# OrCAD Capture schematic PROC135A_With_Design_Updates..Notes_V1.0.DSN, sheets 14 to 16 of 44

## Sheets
14 14. SOC POWER: size C; title: SOC POWER
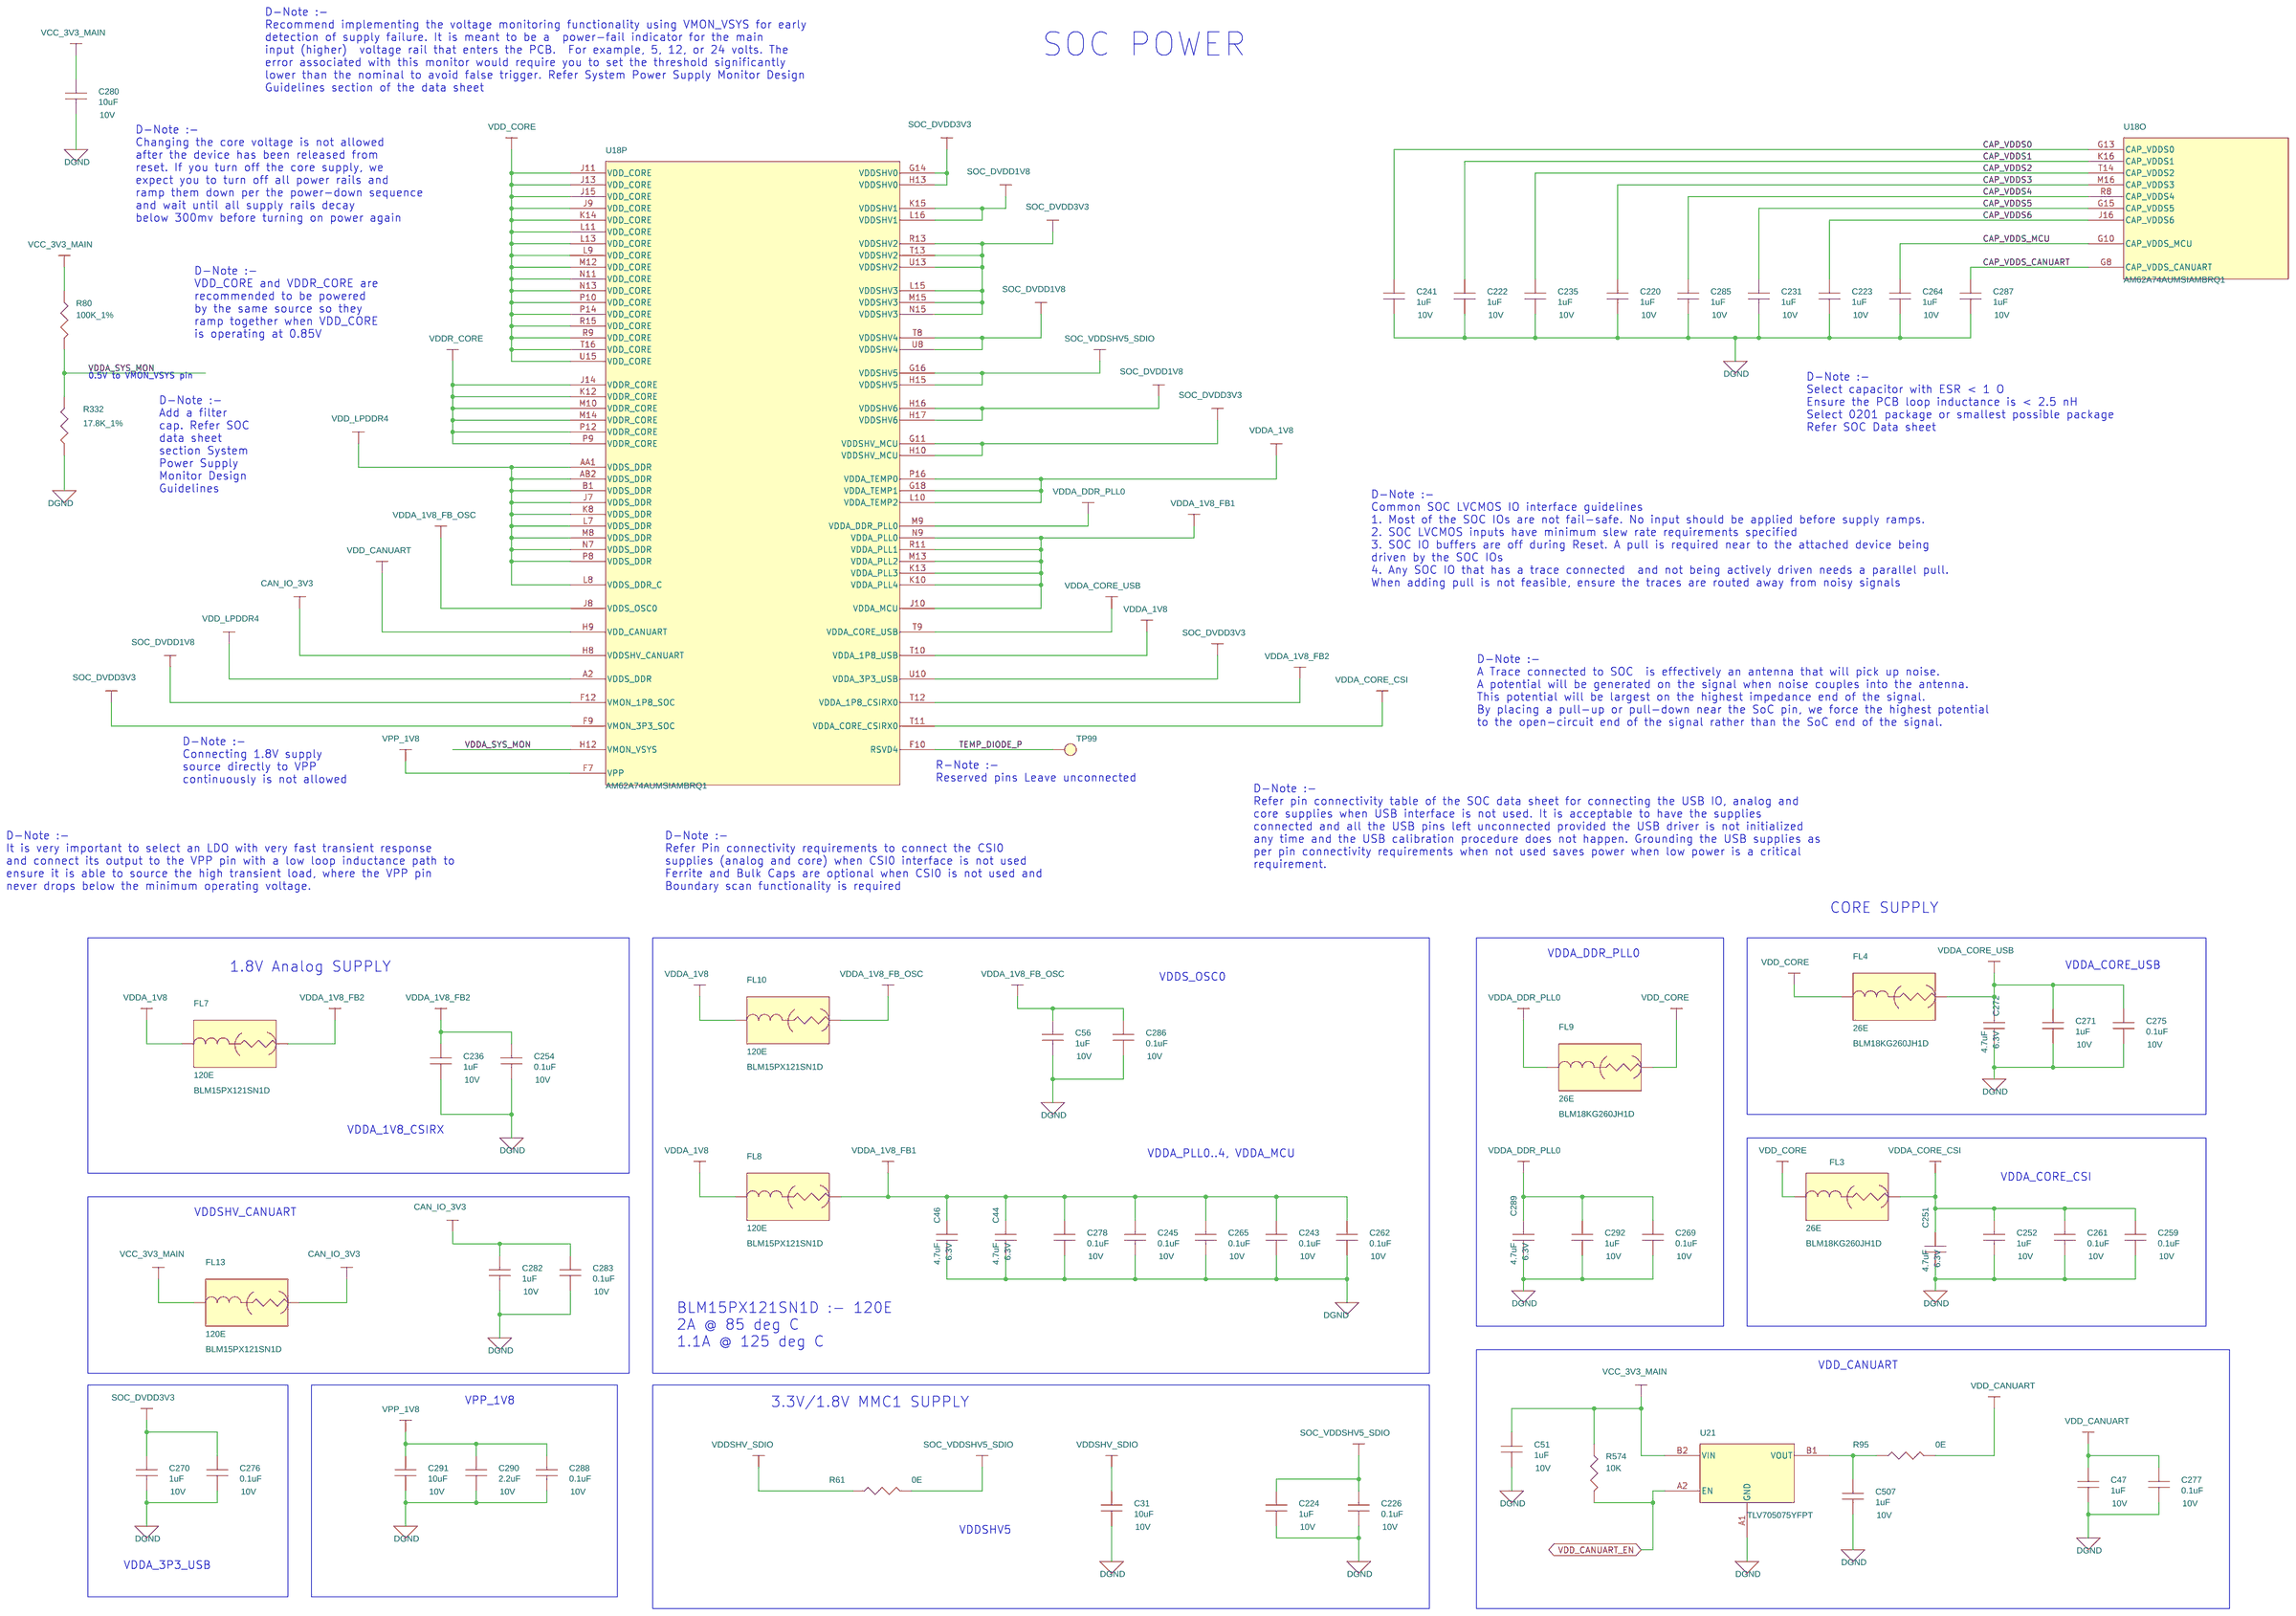
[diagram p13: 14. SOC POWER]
15 15. SOC POWER CAPS: size C; title: SOC POWER CAPS & SOC VSS
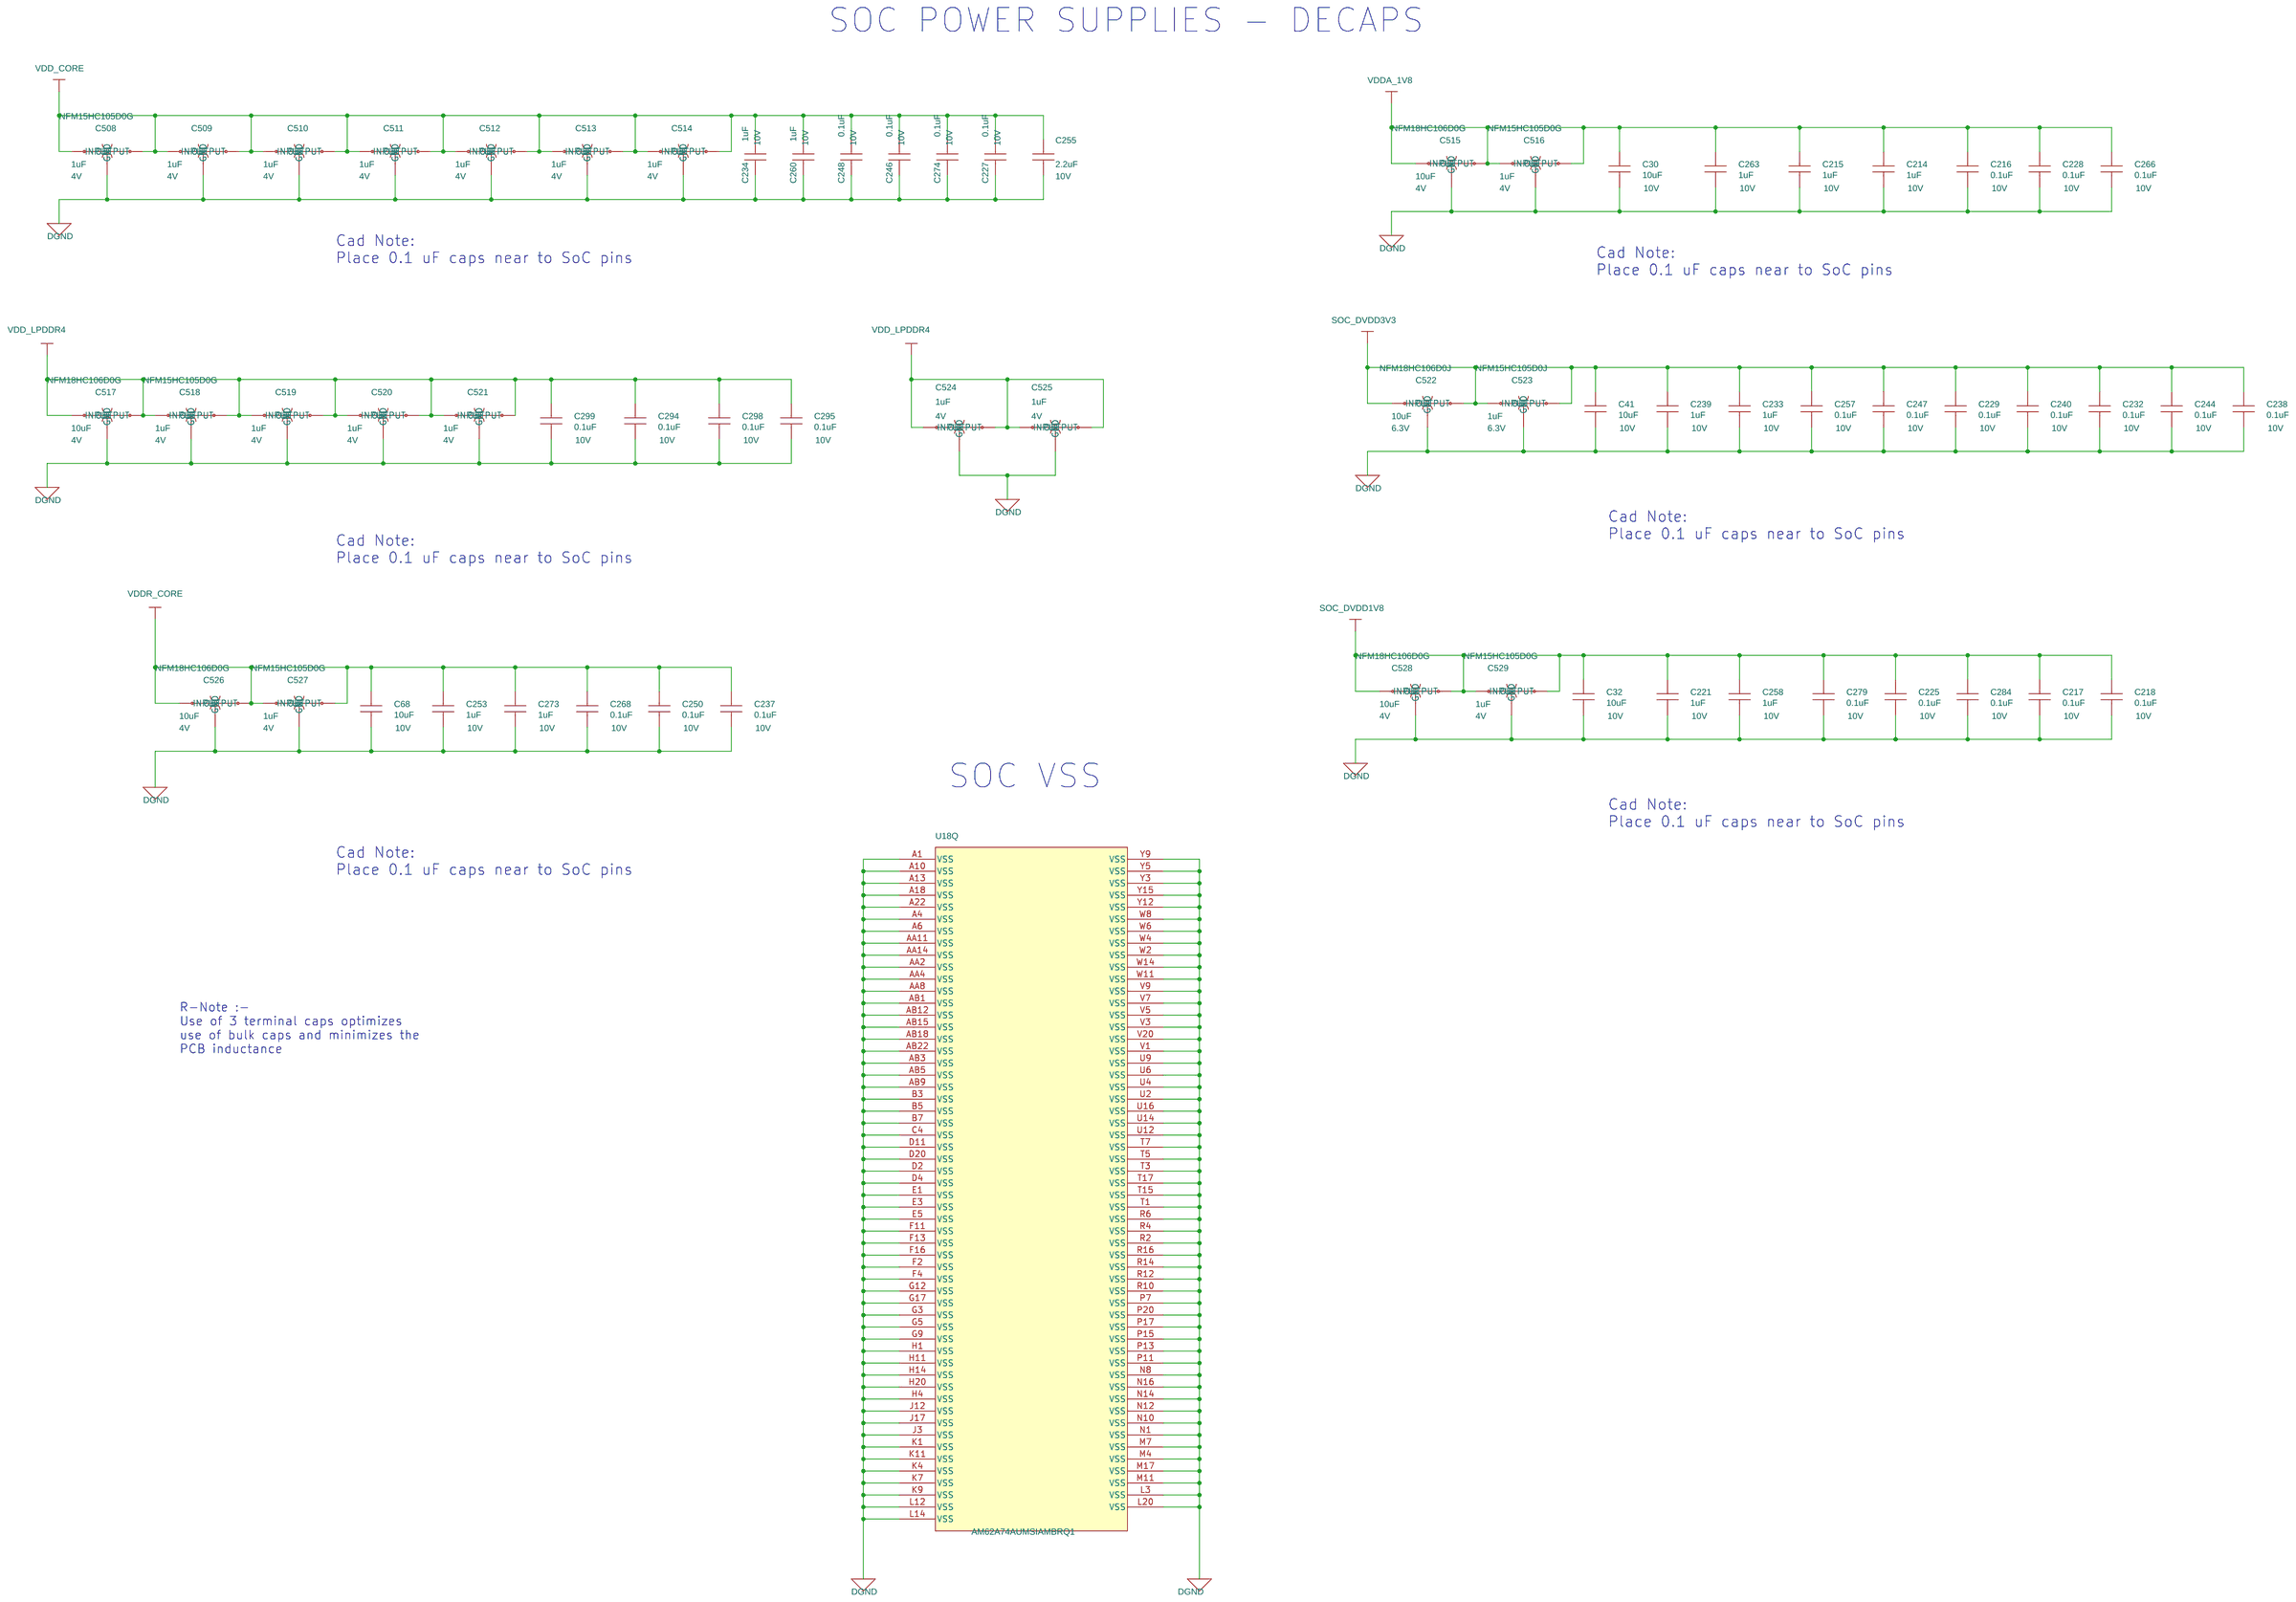
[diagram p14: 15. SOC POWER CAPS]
16 16. LPDDR4 INTERFACE: size C; title: SOC LPDDR4 INTERFACE
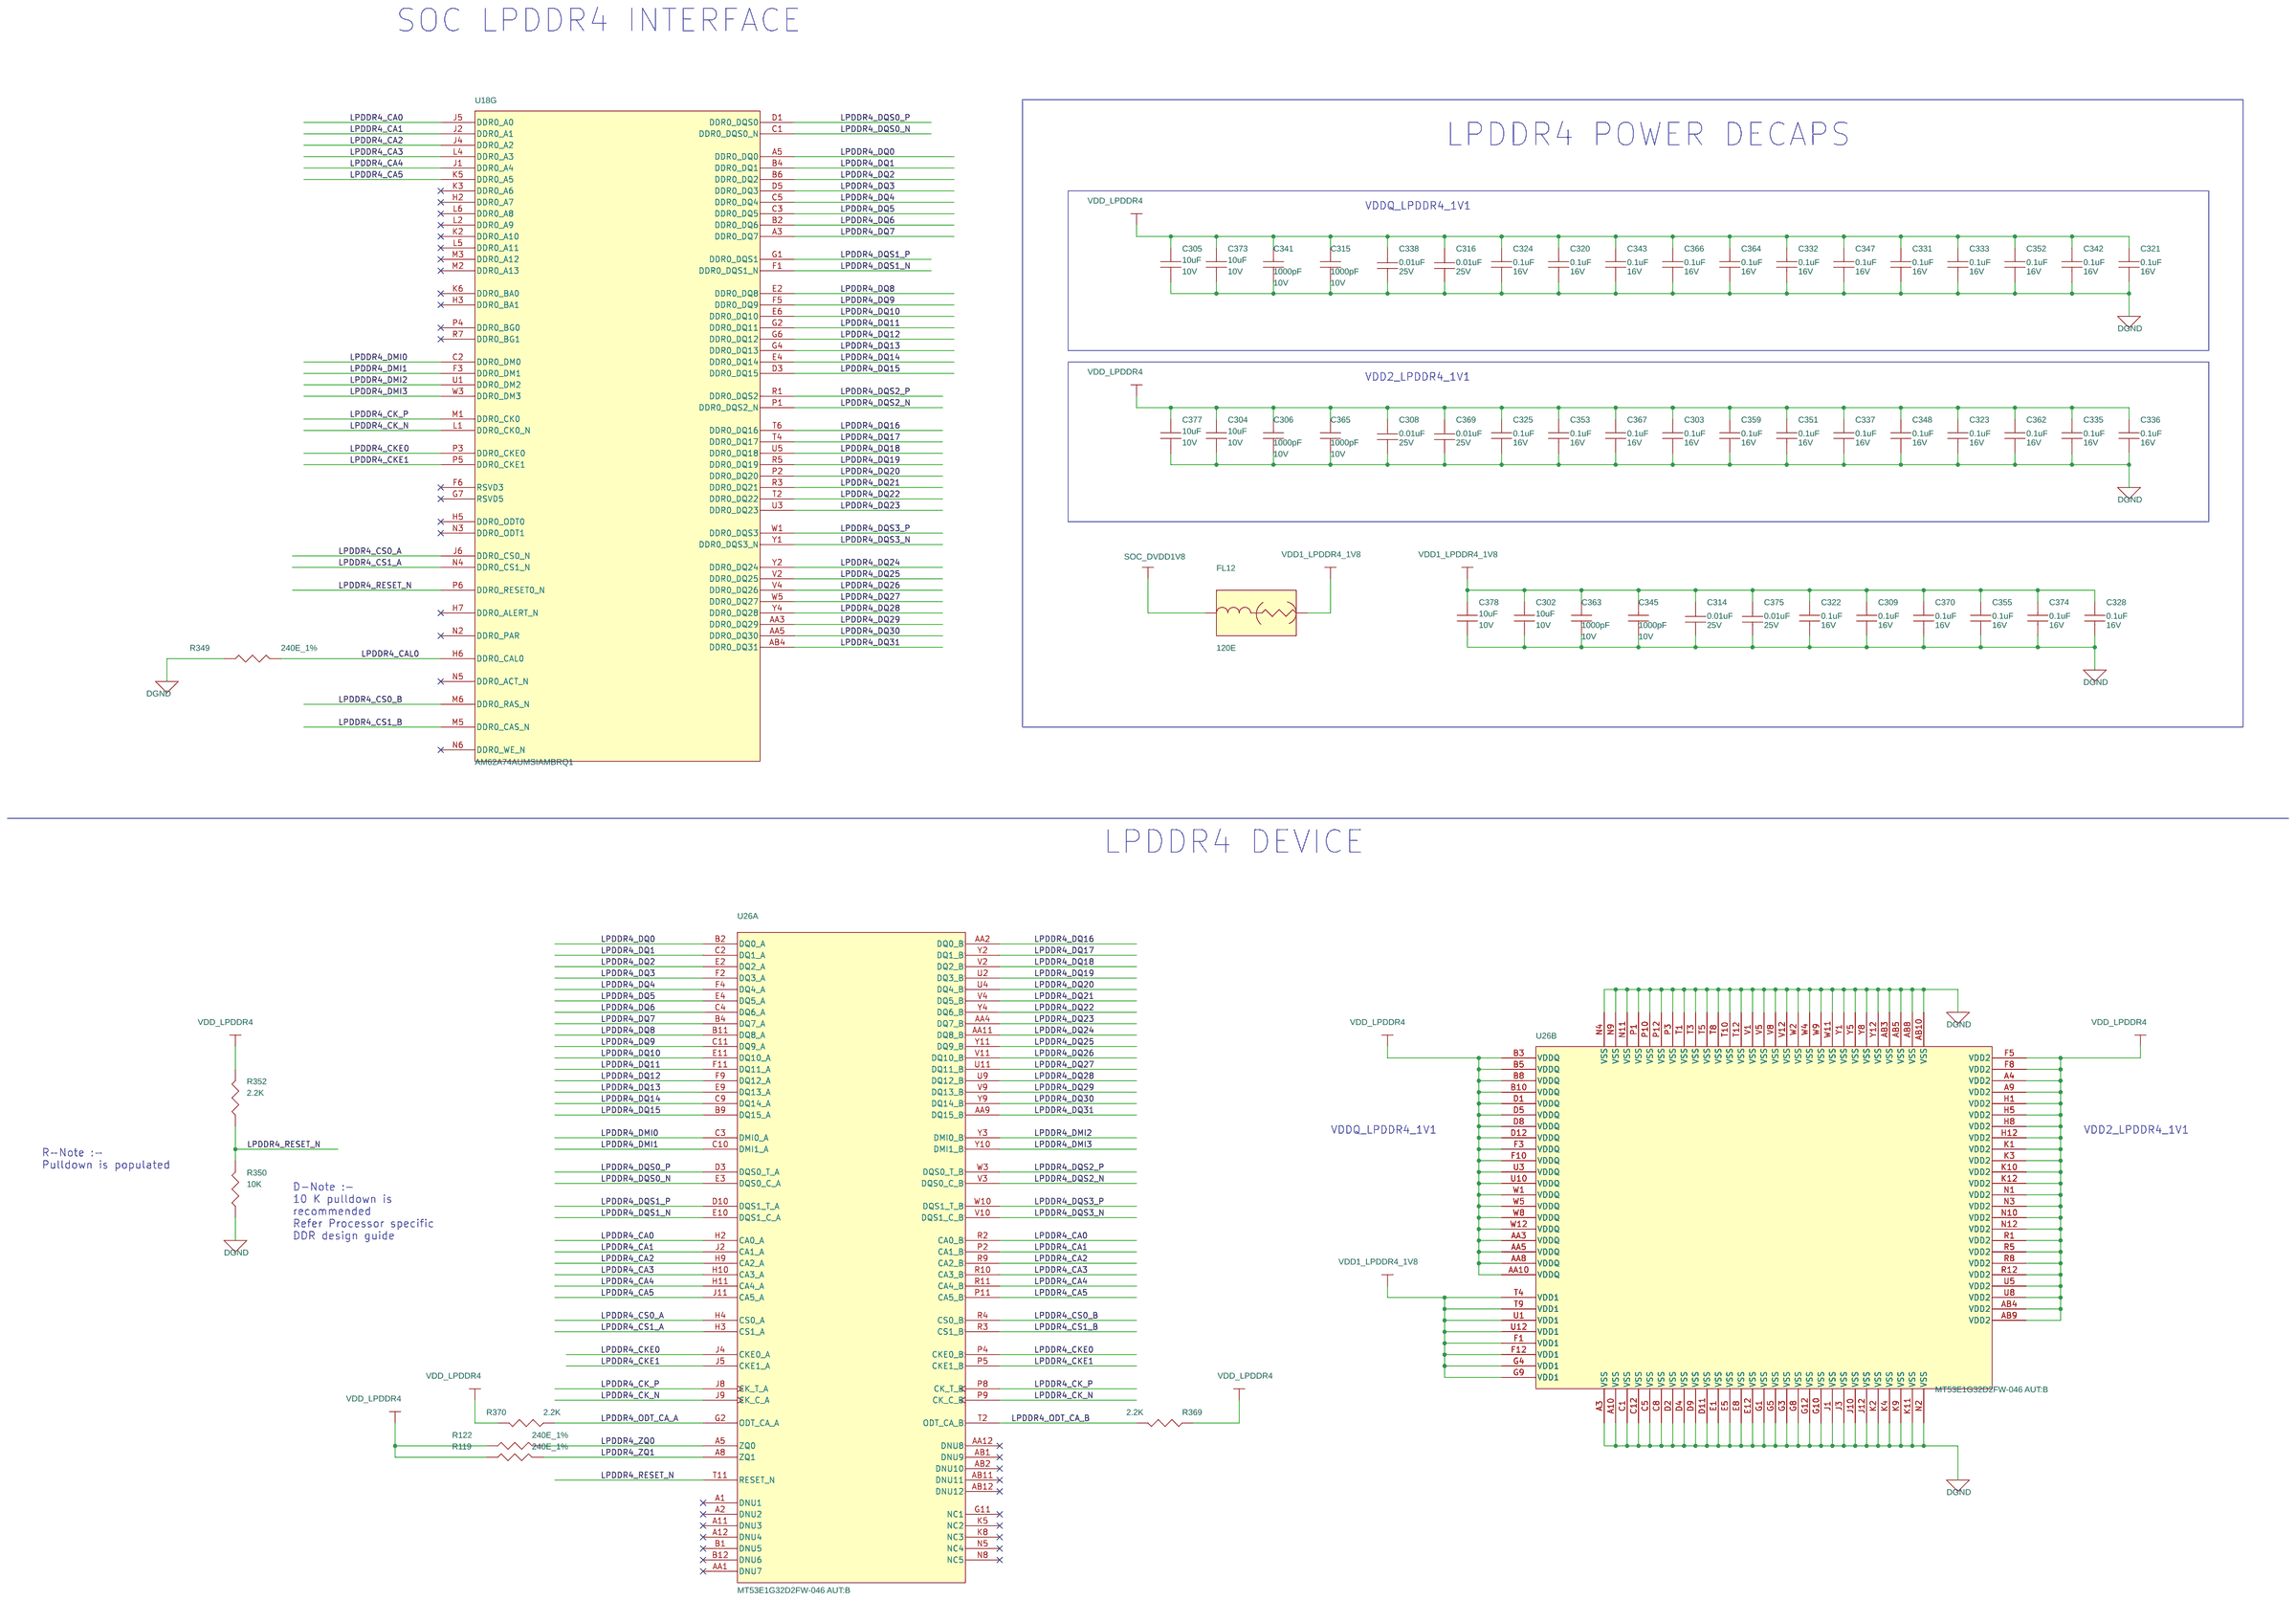
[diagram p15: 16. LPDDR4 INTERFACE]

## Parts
sheet 14. SOC POWER
C31  10uF  [CAP0402_1]
C44  4.7uF  [CAP0201_0-5]
C46  4.7uF  [CAP0201_0-5]
C47  1uF  [CAP0201_0-5]
C51  1uF  [CAP0201_0-5]
C56  1uF  [CAP0201_0-5]
C220  1uF  [CAP0201_0-5]
C222  1uF  [CAP0201_0-5]
C223  1uF  [CAP0201_0-5]
C224  1uF  [CAP0201_0-5]
C226  0.1uF  [CAP0201_0-5]
C231  1uF  [CAP0201_0-5]
C235  1uF  [CAP0201_0-5]
C236  1uF  [CAP0201_0-5]
C241  1uF  [CAP0201_0-5]
C243  0.1uF  [CAP0201_0-5]
C245  0.1uF  [CAP0201_0-5]
C251  4.7uF  [CAP0201_0-5]
C252  1uF  [CAP0201_0-5]
C254  0.1uF  [CAP0201_0-5]
C259  0.1uF  [CAP0201_0-5]
C261  0.1uF  [CAP0201_0-5]
C262  0.1uF  [CAP0201_0-5]
C264  1uF  [CAP0201_0-5]
C265  0.1uF  [CAP0201_0-5]
C269  0.1uF  [CAP0201_0-5]
C270  1uF  [CAP0201_0-5]
C271  1uF  [CAP0201_0-5]
C272  4.7uF  [CAP0201_0-5]
C275  0.1uF  [CAP0201_0-5]
C276  0.1uF  [CAP0201_0-5]
C277  0.1uF  [CAP0201_0-5]
C278  0.1uF  [CAP0201_0-5]
C280  10uF  [CAP0402_1]
C282  1uF  [CAP0201_0-5]
C283  0.1uF  [CAP0201_0-5]
C285  1uF  [CAP0201_0-5]
C286  0.1uF  [CAP0201_0-5]
C287  1uF  [CAP0201_0-5]
C288  0.1uF  [CAP0201_0-5]
C289  4.7uF  [CAP0201_0-5]
C290  2.2uF  [CAP0201_0-5]
C291  10uF  [CAP0402_1]
C292  1uF  [CAP0201_0-5]
C507  1uF  [CAP0201_0-5]
FL3  26E  [EMIFIL_BLM18P_0603_0-8]
FL4  26E  [EMIFIL_BLM18P_0603_0-8]
FL7  120E  [EMIFIL_BLM15A_0402_0-6]
FL8  120E  [EMIFIL_BLM15A_0402_0-6]
FL9  26E  [EMIFIL_BLM18P_0603_0-8]
FL10  120E  [EMIFIL_BLM15A_0402_0-6]
FL13  120E  [EMIFIL_BLM15A_0402_0-6]
R61  0E  [RES0402_0-5]
R80  100K_1%  [RES0402_0-5]
R95  0E  [RES0402_0-5]
R332  17.8K_1%  [RES0402_0-5]
R574  10K  [RES0201_0-5]
TP99  TP20_SMD  [TP20_SMD]
U21  TLV705075YFPT  [DSBGA4_15-74_30X30_0-5]
sheet 15. SOC POWER CAPS
C30  10uF  [CAP0402_1]
C32  10uF  [CAP0402_1]
C41  10uF  [CAP0402_1]
C68  10uF  [CAP0402_1]
C214  1uF  [CAP0201_0-5]
C215  1uF  [CAP0201_0-5]
C216  0.1uF  [CAP0201_0-5]
C217  0.1uF  [CAP0201_0-5]
C218  0.1uF  [CAP0201_0-5]
C221  1uF  [CAP0201_0-5]
C225  0.1uF  [CAP0201_0-5]
C227  0.1uF  [CAP0201_0-5]
C228  0.1uF  [CAP0201_0-5]
C229  0.1uF  [CAP0201_0-5]
C232  0.1uF  [CAP0201_0-5]
C233  1uF  [CAP0201_0-5]
C234  1uF  [CAP0201_0-5]
C237  0.1uF  [CAP0201_0-5]
C238  0.1uF  [CAP0201_0-5]
C239  1uF  [CAP0201_0-5]
C240  0.1uF  [CAP0201_0-5]
C244  0.1uF  [CAP0201_0-5]
C246  0.1uF  [CAP0201_0-5]
C247  0.1uF  [CAP0201_0-5]
C248  0.1uF  [CAP0201_0-5]
C250  0.1uF  [CAP0201_0-5]
C253  1uF  [CAP0201_0-5]
C255  2.2uF  [CAP0201_0-5]
C257  0.1uF  [CAP0201_0-5]
C258  1uF  [CAP0201_0-5]
C260  1uF  [CAP0201_0-5]
C263  1uF  [CAP0201_0-5]
C266  0.1uF  [CAP0201_0-5]
C268  0.1uF  [CAP0201_0-5]
C273  1uF  [CAP0201_0-5]
C274  0.1uF  [CAP0201_0-5]
C279  0.1uF  [CAP0201_0-5]
C284  0.1uF  [CAP0201_0-5]
C294  0.1uF  [CAP0201_0-5]
C295  0.1uF  [CAP0201_0-5]
C298  0.1uF  [CAP0201_0-5]
C299  0.1uF  [CAP0201_0-5]
C508  1uF  [EMIFIL_NFM15CC_0402_0-5]
C509  1uF  [EMIFIL_NFM15CC_0402_0-5]
C510  1uF  [EMIFIL_NFM15CC_0402_0-5]
C511  1uF  [EMIFIL_NFM15CC_0402_0-5]
C512  1uF  [EMIFIL_NFM15CC_0402_0-5]
C513  1uF  [EMIFIL_NFM15CC_0402_0-5]
C514  1uF  [EMIFIL_NFM15CC_0402_0-5]
C515  10uF  [EMIFIL_NFM18C_0603_0-7]
C516  1uF  [EMIFIL_NFM15CC_0402_0-5]
C517  10uF  [EMIFIL_NFM18C_0603_0-7]
C518  1uF  [EMIFIL_NFM15CC_0402_0-5]
C519  1uF  [EMIFIL_NFM15CC_0402_0-5]
C520  1uF  [EMIFIL_NFM15CC_0402_0-5]
C521  1uF  [EMIFIL_NFM15CC_0402_0-5]
C522  10uF  [EMIFIL_NFM18C_0603_0-7]
C523  1uF  [EMIFIL_NFM15CC_0402_0-5]
C524  1uF  [EMIFIL_NFM15CC_0402_0-5]
C525  1uF  [EMIFIL_NFM15CC_0402_0-5]
C526  10uF  [EMIFIL_NFM18C_0603_0-7]
C527  1uF  [EMIFIL_NFM15CC_0402_0-5]
C528  10uF  [EMIFIL_NFM18C_0603_0-7]
C529  1uF  [EMIFIL_NFM15CC_0402_0-5]
sheet 16. LPDDR4 INTERFACE
C302  10uF  [CAP0402_0-75]
C303  0.1uF  [CAP0201_0-5]
C304  10uF  [CAP0402_0-75]
C305  10uF  [CAP0402_0-75]
C306  1000pF  [CAP0201_0-5]
C308  0.01uF  [CAP0201_0-5]
C309  0.1uF  [CAP0201_0-5]
C314  0.01uF  [CAP0201_0-5]
C315  1000pF  [CAP0201_0-5]
C316  0.01uF  [CAP0201_0-5]
C320  0.1uF  [CAP0201_0-5]
C321  0.1uF  [CAP0201_0-5]
C322  0.1uF  [CAP0201_0-5]
C323  0.1uF  [CAP0201_0-5]
C324  0.1uF  [CAP0201_0-5]
C325  0.1uF  [CAP0201_0-5]
C328  0.1uF  [CAP0201_0-5]
C331  0.1uF  [CAP0201_0-5]
C332  0.1uF  [CAP0201_0-5]
C333  0.1uF  [CAP0201_0-5]
C335  0.1uF  [CAP0201_0-5]
C336  0.1uF  [CAP0201_0-5]
C337  0.1uF  [CAP0201_0-5]
C338  0.01uF  [CAP0201_0-5]
C341  1000pF  [CAP0201_0-5]
C342  0.1uF  [CAP0201_0-5]
C343  0.1uF  [CAP0201_0-5]
C345  1000pF  [CAP0201_0-5]
C347  0.1uF  [CAP0201_0-5]
C348  0.1uF  [CAP0201_0-5]
C351  0.1uF  [CAP0201_0-5]
C352  0.1uF  [CAP0201_0-5]
C353  0.1uF  [CAP0201_0-5]
C355  0.1uF  [CAP0201_0-5]
C359  0.1uF  [CAP0201_0-5]
C362  0.1uF  [CAP0201_0-5]
C363  1000pF  [CAP0201_0-5]
C364  0.1uF  [CAP0201_0-5]
C365  1000pF  [CAP0201_0-5]
C366  0.1uF  [CAP0201_0-5]
C367  0.1uF  [CAP0201_0-5]
C369  0.01uF  [CAP0201_0-5]
C370  0.1uF  [CAP0201_0-5]
C373  10uF  [CAP0402_0-75]
C374  0.1uF  [CAP0201_0-5]
C375  0.01uF  [CAP0201_0-5]
C377  10uF  [CAP0402_0-75]
C378  10uF  [CAP0402_0-75]
FL12  120E  [EMIFIL_BLM15A_0402_0-6]
R119  240E_1%  [RES0402_0-5]
R122  240E_1%  [RES0402_0-5]
R349  240E_1%  [RES0402_0-5]
R350  10K  [RES0402_0-5]
R352  2.2K  [RES0402_0-5]
R369  2.2K  [RES0402_0-5]
R370  2.2K  [RES0402_0-5]
U26  MT53E1G32D2FW-046 AUT:B  [WFBGA200_MT53E2G32D4DE_400X570_1-2]  (sections A,B)
sheet 41. OSCILLATOR
U18  AM62A74AUMSIAMBRQ1  [FBGA484_31-49_710X710_2-7]  (sections A,B,C,D,E,F,G,H,I,J,K,L,M,N,O,P,Q)

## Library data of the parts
C30-C32 C41 C68 C280 C291 = CAP: CAP CERAMIC 10uF 10V 20% X5R 0402; Chkd/date: MANIRAJA/150219; Crtd /date: ALVY/150219; Custom_Duty: 15%; Customs_HS_Code: 85322990; Distributor_name: DIGIKEY; Distributor_part_number: 1276-6830-1-ND; Footprint Path: Y:\MIS_DATABASE\Library\ALTIUM_TOOL\PCB_FOOTPRINTS\Altium_Footprint_Lib.PcbLib; Height: 0.90MM; Library Path: Y:\MIS_DATABASE\Library\ALTIUM_TOOL\SCHEMATICS_PARTS\MS_DISCRETE_Library.schlib; Mfr_name: SAMSUNG; Mfr_part_number: CL05A106MP8NUB8; Mistral Part No: 120019020008-R; Package: 0402; Part_type: CAPACITORS\CERAMIC; Project: TI_60GHz-AOP; RoHS: RoHS; Temperature: -55°C+85°C; Tolerance: 20%; Voltage: 10V; Wattage: NA; Weight: NA; Datasheet: Y:\MIS_DATABASE\DATASHEETS\CAPACITORS\CL05A106MP8NUB8.PDF
C44 C46 C251 C272 C289 = CAP: CAP CERAMIC 4.7uF 6.3V 20% X5R 0201; Chkd/date: ALVY/020522; Crtd /date: TAMILARASU/020522; Custom_Duty: 15%; Customs_HS_Code: 85322990; Distributor_name: NA; Distributor_part_number: NA; Footprint Path: Y:\MIS_DATABASE\Library\ALTIUM_TOOL\PCB_FOOTPRINTS\Altium_Footprint_Lib.PcbLib; Height: 0.33MM; Library Path: Y:\MIS_DATABASE\Library\ALTIUM_TOOL\SCHEMATICS_PARTS\MS_DISCRETE_Library.schlib; Mfr_name: CAL-CHIP; Mfr_part_number: GMC02X5R475M6R3NT; Mistral Part No: 120022050001-R; Package: 0201; Part_type: CAPACITORS\CERAMIC; Project: TI_AM62A_SK_EVM; RoHS: RoHS; Temperature: -55°C+85°C; Tolerance: 20%; Voltage: 6.3V; Wattage: NA; Weight: NA; Datasheet: Y:\MIS_DATABASE\DATASHEETS\CAPACITORS\CALCHIP-GMC-SER.PDF
C47 C51 C56 C214 C215 C220-C224 C231 C233-C236 C239 C241 C252 C253 C258 C260 C263 C264 C270 C271 C273 C282 C285 C287 C292 C507 = CAP: CAP CERAMIC 1uF 10V 20% X5R 0201; Chkd/date: NAVEED/070415; Crtd /date: VASANTHA/230314; Custom_Duty: 15%; Customs_HS_Code: 85322990; Distributor_name: DIGIKEY; Distributor_part_number: 1276-1324-1-ND; Footprint Path: Y:\MIS_DATABASE\Library\ALTIUM_TOOL\PCB_FOOTPRINTS\Altium_Footprint_Lib.PcbLib; Height: 0.35MM; Library Path: Y:\MIS_DATABASE\Library\ALTIUM_TOOL\SCHEMATICS_PARTS\MS_DISCRETE_Library.schlib; Mfr_name: SAMSUNG; Mfr_part_number: CL03A105MP3NSNC; Mistral Part No: 120015030003-R; Package: 0201; Part_type: CAPACITORS\CERAMIC; Project: DUET BOARDS; RoHS: RoHS; Temperature: -55°C+85°C; Tolerance: 20%; Voltage: 10V; Wattage: NA; Weight: 0.17mg; Datasheet: Y:\MIS_DATABASE\DATASHEETS\CAPACITORS\CL03A105MP3NSNC.PDF
C216-C218 C225-C229 C232 C237 C238 C240 C243-C248 C250 C254 C257 C259 C261 C262 C265 C266 C268 C269 C274-C279 C283 C284 C286 C294 C295 C298 C299 = CAP: CAP CERAMIC 0.1uF 10V 10% X5R 0201; Chkd/date: MANIRAJA/290421; Crtd /date: ALVY/290421; Custom_Duty: 15%; Customs_HS_Code: 85322990; Distributor_name: DIGIKEY; Distributor_part_number: 1276-1115-1-ND; Footprint Path: Y:\MIS_DATABASE\Library\ALTIUM_TOOL\PCB_FOOTPRINTS\Altium_Footprint_Lib.PcbLib; Height: 0.33MM; Library Path: Y:\MIS_DATABASE\Library\ALTIUM_TOOL\SCHEMATICS_PARTS\MS_DISCRETE_Library.schlib; Mfr_name: SAMSUNG; Mfr_part_number: CL03A104KP3NNNC; Mistral Part No: 120009050017-R; Package: 0201; Part_type: CAPACITORS\CERAMIC; Project: SRMS-SAR_BRD; RoHS: RoHS; Temperature: -55°C+85°C; Tolerance: 10%; Voltage: 10V; Wattage: NA; Weight: 0.33mg; Datasheet: Y:\MIS_DATABASE\DATASHEETS\CAPACITORS\CL03A104KP3NNNC.PDF
C288 = CAP: CAP CERAMIC 0.1uF 10V 20% X5R 0201; Chkd/date: RAGESH/290910; Crtd /date: MUDDU/290410; Custom_Duty: 15%; Customs_HS_Code: 85322990; Distributor_name: DIGIKEY; Distributor_part_number: 490-5405-1-ND; Footprint Path: Y:\MIS_DATABASE\Library\ALTIUM_TOOL\PCB_FOOTPRINTS\Altium_Footprint_Lib.PcbLib; Height: 0.33MM; Library Path: Y:\MIS_DATABASE\Library\ALTIUM_TOOL\SCHEMATICS_PARTS\MS_DISCRETE_Library.schlib; Mfr_name: MURATA; Mfr_part_number: GRM033R61A104ME15D; Mistral Part No: 120010040004-R; Package: 0201; Part_type: CAPACITORS\CERAMIC; Project: BUG_BASE-II; RoHS: RoHS; Temperature: -55°C+85°C; Tolerance: 20%; Voltage: 10V; Wattage: NA; Weight: 0.33mg; Datasheet: Y:\MIS_DATABASE\DATASHEETS\CAPACITORS\MURATA-GXX-SER_NOV17.PDF
C290 = CAP: CAP CERAMIC 2.2uF 10V 20% X5R 0201; Chkd/date: MANIRAJA/270519; Crtd /date: ALVY/230519; Custom_Duty: 15%; Customs_HS_Code: 85322990; Distributor_name: DIGIKEY; Distributor_part_number: 490-13228-1-ND; Footprint Path: Y:\MIS_DATABASE\Library\ALTIUM_TOOL\PCB_FOOTPRINTS\Altium_Footprint_Lib.PcbLib; Height: 0.39MM; Library Path: Y:\MIS_DATABASE\Library\ALTIUM_TOOL\SCHEMATICS_PARTS\MS_DISCRETE_Library.schlib; Mfr_name: MURATA; Mfr_part_number: GRM033R61A225ME47D; Mistral Part No: 120019050028-R; Package: 0201; Part_type: CAPACITORS\CERAMIC; Project: BRUKER_SD820_COMMONDO; RoHS: RoHS; Temperature: -55°C+85°C; Tolerance: 20%; Voltage: 10V; Wattage: NA; Weight: 0.33mg; Datasheet: Y:\MIS_DATABASE\DATASHEETS\CAPACITORS\GRM033R61A225ME47D.PDF
FL3 FL4 FL9 = EMIFILTER_IND: IND FERRITE BEAD CHIP 26E 4A 0603; Chkd/date: ALVY/020522; Crtd /date: TAMILARASU/020522; Custom_Duty: 24%; Customs_HS_Code: 85437099; Distributor_name: DIGIKEY; Distributor_part_number: 490-14026-1-ND; Footprint Path: Y:\MIS_DATABASE\Library\ALTIUM_TOOL\PCB_FOOTPRINTS\Altium_Footprint_Lib.PcbLib; Height: 0.75MM; Library Path: Y:\MIS_DATABASE\Library\ALTIUM_TOOL\SCHEMATICS_PARTS\MS_FILTER_Library.schlib; Mfr_name: MURATA; Mfr_part_number: BLM18KG260JH1D; Mistral Part No: 130022050001-R; Package: 0603; Part_type: INDUCTOR; Project: TI_AM62A_SK_EVM; RoHS: RoHS; Temperature: -55°C+150°C; Tolerance: 25%; Voltage: NA; Wattage: NA; Weight: 4mg; Datasheet: Y:\MIS_DATABASE\DATASHEETS\DISCRETES\INDUCTORS\BLM18XX-B-J-H1D.PDF
FL7 FL8 FL10 FL12 FL13 = EMIFILTER_IND: IND FERRITE BEAD CHIP 120E 2A 0402; Chkd/date: NAVEED/241114; Crtd /date: USMAN/170613; Custom_Duty: 24%; Customs_HS_Code: 85369090; Distributor_name: DIGIKEY; Distributor_part_number: 490-9656-1-ND; Footprint Path: Y:\MIS_DATABASE\Library\ALTIUM_TOOL\PCB_FOOTPRINTS\Altium_Footprint_Lib.PcbLib; Height: 0.55MM; Library Path: Y:\MIS_DATABASE\Library\ALTIUM_TOOL\SCHEMATICS_PARTS\MS_FILTER_Library.schlib; Mfr_name: MURATA; Mfr_part_number: BLM15PX121SN1D; Mistral Part No: 130013060022-R; Package: 0402; Part_type: INDUCTOR; Project: GEN_3-8; RoHS: RoHS; Temperature: -55°C+125°C; Tolerance: 25%; Voltage: NA; Wattage: NA; Weight: 1mg; Datasheet: Y:\MIS_DATABASE\DATASHEETS\DISCRETES\INDUCTORS\BLM15-SN1-SER.PDF
R61 R95 = RESISTOR: RES 0E 1/10W JUMPER 0402; Chkd/date: VASANTHA/061216; Crtd /date: NAVEED/201014; Custom_Duty: 15%; Customs_HS_Code: 85332119; Distributor_name: DIGIKEY; Distributor_part_number: P0.0JCT-ND; Footprint Path: Y:\MIS_DATABASE\Library\ALTIUM_TOOL\PCB_FOOTPRINTS\Altium_Footprint_Lib.PcbLib; Height: 0.40MM; IBISSP_MODLES: VALUE REPEATING 2 TIME; Library Path: Y:\MIS_DATABASE\Library\ALTIUM_TOOL\SCHEMATICS_PARTS\MS_DISCRETE_Library.schlib; Mfr_name: PANASONIC-ECG; Mfr_part_number: ERJ-2GE0R00X; Mistral Part No: 110018030052-R; Package: 0402; Part_type: RESISTORS\FIXED; Project: AEGIS POM; RoHS: RoHS; Temperature: -55°C+155°C; Tolerance: NA; Voltage: NA; Wattage: 1/10W; Weight: 0.8mg; Datasheet: Y:\MIS_DATABASE\DATASHEETS\RESISTORS\PAN-ERJSER_NOV17.PDF
R80 = RESISTOR: RES 100K 1/10W 1% 0402; Chkd/date: VASANTHA/201216; Crtd /date: MAZHAR/130306; Custom_Duty: 15%; Customs_HS_Code: 85332119; Distributor_name: DIGIKEY; Distributor_part_number: P100KLCT-ND; Footprint Path: Y:\MIS_DATABASE\Library\ALTIUM_TOOL\PCB_FOOTPRINTS\Altium_Footprint_Lib.PcbLib; Height: 0.40MM; Library Path: Y:\MIS_DATABASE\Library\ALTIUM_TOOL\SCHEMATICS_PARTS\MS_DISCRETE_Library.schlib; Mfr_name: PANASONIC-ECG; Mfr_part_number: ERJ-2RKF1003X; Mistral Part No: 110009030187-R; Package: 0402; Part_type: RESISTORS\FIXED; Project: J32; RoHS: RoHS; Temperature: -55°C+155°C; Tolerance: 1%; Voltage: NA; Wattage: 1/10W; Weight: 0.8mg; Datasheet: Y:\MIS_DATABASE\DATASHEETS\RESISTORS\PAN-ERJSER_NOV17.PDF
R332 = RESISTOR: RES 17.8K 1/16W 1% 0402; Chkd/date: MANIRAJA/160218; Crtd /date: ALVY/150218; Custom_Duty: 15%; Customs_HS_Code: 85332119; Distributor_name: DIGIKEY; Distributor_part_number: 541-17.8KLCT-ND; Footprint Path: Y:\MIS_DATABASE\Library\ALTIUM_TOOL\PCB_FOOTPRINTS\Altium_Footprint_Lib.PcbLib; Height: 0.40MM; Library Path: Y:\MIS_DATABASE\Library\ALTIUM_TOOL\SCHEMATICS_PARTS\MS_DISCRETE_Library.schlib; Manufacturer: VISHAY; Mfr_name: VISHAY; Mfr_part_number: CRCW040217K8FKED; Mistral Part No: 110018020020-R; Package: 0402; Part_type: RESISTORS\FIXED; Project: DRDL_ITS2-SC; RoHS: RoHS; Temperature: -55°C+155°C; Tolerance: 1%; Voltage: NA; Wattage: 1/16W; Weight: 0.65mg; Datasheet: Y:\MIS_DATABASE\DATASHEETS\RESISTORS\CRCW0603.PDF
R574 = RESISTOR: RES 10K 1/20W 5% 0201; Chkd/date: MANIRAJA/050517; Crtd /date: MANIRAJA/050517; Custom_Duty: 15%; Customs_HS_Code: 85332119; Distributor_name: DIGIKEY; Distributor_part_number: 311-10KNCT-ND; Footprint Path: Y:\MIS_DATABASE\Library\ALTIUM_TOOL\PCB_FOOTPRINTS\Altium_Footprint_Lib.PcbLib; Height: 0.26MM; Library Path: Y:\MIS_DATABASE\Library\ALTIUM_TOOL\SCHEMATICS_PARTS\MS_DISCRETE_Library.schlib; Mfr_name: YAGEO AMERICA; Mfr_part_number: RC0201JR-0710KL; Mistral Part No: 110010070051-R; Package: 0201; Part_type: RESISTORS\FIXED; Project: GOLDEN-I LITE; RoHS: RoHS; Temperature: -55°C+125°C; Tolerance: 5%; Voltage: NA; Wattage: 1/20W; Weight: 0.17mg; Datasheet: Y:\MIS_DATABASE\DATASHEETS\RESISTORS\RCXXXXL-SER_MAR18.PDF
TP99 = TESTPOINT: TESTPOINT CIR 20 SMD; Chkd/date: SHREESHAIL/171006; Crtd /date: MAZHAR/171006; Custom_Duty: NA; Customs_HS_Code: NA; Distributor_name: NA; Distributor_part_number: NA; Footprint Path: Y:\MIS_DATABASE\Library\ALTIUM_TOOL\PCB_FOOTPRINTS\Altium_Footprint_Lib.PcbLib; Height: NA; Library Path: Y:\MIS_DATABASE\Library\ALTIUM_TOOL\SCHEMATICS_PARTS\MS_DISCRETE_Library.schlib; MECHANICAL 3D STEP FILE: NA; Mfr_name: LOCAL; Mistral Part No: NA; Package: SMD; Project: BT MODULE_CSRBC04; RoHS: NA; Temperature: NA; Tolerance: NA; Voltage: NA; Wattage: NA; Weight: NA; Datasheet: NA
U21 = TLV7050_DSBGA4: IC 200mA 0.75V LOW IQ LOW-DROPOUT REGULATOR DSBGA4; Chkd/date: ALVY/300522; Crtd /date: TAMILARASU/300522; Custom_Duty: 15%; Customs_HS_Code: 85423100; Distributor_name: DIGIKEY; Distributor_part_number: 296-TLV705075YFPTCT-ND; Footprint Path: Y:\MIS_DATABASE\Library\ALTIUM_TOOL\PCB_FOOTPRINTS\Altium_Footprint_Lib.PcbLib; Height: 0.50MM; Library Path: Y:\MIS_DATABASE\Library\ALTIUM_TOOL\SCHEMATICS_PARTS\MS_MISCPOWER_Library.schlib; Mfr_name: TEXAS INSTRUMENTS; Mistral Part No: 142022050034-R; Package: DSBGA4; Part_type: ICS\POWER\VOLTAGE REGULATOR; Project: TI_AM62A_SK_EVM; RoHS: RoHS; Temperature: -40°C+125°C; Tolerance: NA; Voltage: NA; Wattage: NA; Weight: 200mg; Datasheet: Y:\MIS_DATABASE\DATASHEETS\ICS\POWER\TLV705X.PDF
C255 = CAP: CAP CERAMIC 2.2uF 10V 10% X5R 0201; Chkd/date: MANIRAJA/220918; Crtd /date: MANIRAJA/220918; Custom_Duty: 15%; Customs_HS_Code: 85322990; Distributor_name: DIGIKEY; Distributor_part_number: 490-13227-1-ND; Footprint Path: Y:\MIS_DATABASE\Library\ALTIUM_TOOL\PCB_FOOTPRINTS\Altium_Footprint_Lib.PcbLib; Height: 0.39MM; Library Path: Y:\MIS_DATABASE\Library\ALTIUM_TOOL\SCHEMATICS_PARTS\MS_DISCRETE_Library.schlib; Mfr_name: MURATA; Mfr_part_number: GRM033R61A225KE47D; Mistral Part No: 120018090044-R; Package: 0201; Part_type: CAPACITORS\CERAMIC; Project: TI_60GHz-AOP; RoHS: RoHS; Temperature: -55°C+85°C; Tolerance: 10%; Voltage: 10V; Wattage: NA; Weight: 0.33mg; Datasheet: Y:\MIS_DATABASE\DATASHEETS\CAPACITORS\GRM033R61A225KE47D.PDF
C508-C514 C516 C518-C521 C524 C525 C527 C529 = CAP_NFM: PASSIVE FILTER EMI 1uF 4V AUTO 0402; Chkd/date: MANIRAJA/251018; Crtd /date: ALVY/251018; Custom_Duty: 15%; Customs_HS_Code: 85412900; Distributor_name: NA; Distributor_part_number: NA; Footprint Path: Y:\MIS_DATABASE\Library\ALTIUM_TOOL\PCB_FOOTPRINTS\Altium_Footprint_Lib.PcbLib; Height: 0.50MM; Library Path: Y:\MIS_DATABASE\Library\ALTIUM_TOOL\SCHEMATICS_PARTS\MS_FILTER_Library.schlib; Mfr_name: MURATA; Mfr_part_number: NFM15HC105D0G; Mistral Part No: 130018100050; Package: 0402; Part_type: FILTER; Project: TI_J7ES_EVM_SOM; RoHS: NA; Temperature: NA; Tolerance: NA; Voltage: 4V; Wattage: NA; Weight: NA; Datasheet: Y:\MIS_DATABASE\DATASHEETS\DISCRETES\INDUCTORS\NFM15CC223C1A3.PDF
C515 C517 C526 C528 = CAP_NFM: PASSIVE FILTER EMI 10uF 4V AUTO 0603; Chkd/date: MANIRAJA/251018; Crtd /date: ALVY/251018; Custom_Duty: 15%; Customs_HS_Code: 85412900; Distributor_name: NA; Distributor_part_number: NA; Footprint Path: Y:\MIS_DATABASE\Library\ALTIUM_TOOL\PCB_FOOTPRINTS\Altium_Footprint_Lib.PcbLib; Height: 0.70MM; Library Path: Y:\MIS_DATABASE\Library\ALTIUM_TOOL\SCHEMATICS_PARTS\MS_FILTER_Library.schlib; Mfr_name: MURATA; Mfr_part_number: NFM18HC106D0G; Mistral Part No: 130018100049; Package: 0603; Part_type: FILTER; Project: TI_J7ES_EVM_SOM; RoHS: NA; Temperature: NA; Tolerance: NA; Voltage: 4V; Wattage: NA; Weight: NA; Datasheet: Y:\MIS_DATABASE\DATASHEETS\DISCRETES\INDUCTORS\NFM18HC-SER.PDF
C522 = CAP_NFM: PASSIVE FILTER EMI 10uF 6.3V AUTO 0603; Chkd/date: MANIRAJA/280918; Crtd /date: ALVY/280918; Custom_Duty: 15%; Customs_HS_Code: 85412900; Distributor_name: NA; Distributor_part_number: NA; Footprint Path: Y:\MIS_DATABASE\Library\ALTIUM_TOOL\PCB_FOOTPRINTS\Altium_Footprint_Lib.PcbLib; Height: 0.70MM; Library Path: Y:\MIS_DATABASE\Library\ALTIUM_TOOL\SCHEMATICS_PARTS\MS_FILTER_Library.schlib; Mfr_name: MURATA; Mfr_part_number: NFM18HC106D0J; Mistral Part No: 130018090051; Package: 0603; Part_type: FILTER; Project: TI_J7_SVB-DUT; RoHS: NA; Temperature: NA; Tolerance: NA; Voltage: 6.3V; Wattage: NA; Weight: NA; Datasheet: Y:\MIS_DATABASE\DATASHEETS\DISCRETES\INDUCTORS\NFM18HC-SER.PDF
C523 = CAP_NFM: PASSIVE FILTER EMI 1uF 6.3V AUTO 0402; Chkd/date: MANIRAJA/280918; Crtd /date: ALVY/280918; Custom_Duty: 15%; Customs_HS_Code: 85412900; Distributor_name: NA; Distributor_part_number: NA; Footprint Path: Y:\MIS_DATABASE\Library\ALTIUM_TOOL\PCB_FOOTPRINTS\Altium_Footprint_Lib.PcbLib; Height: 0.50MM; Library Path: Y:\MIS_DATABASE\Library\ALTIUM_TOOL\SCHEMATICS_PARTS\MS_FILTER_Library.schlib; Mfr_name: MURATA; Mfr_part_number: NFM15HC105D0J; Mistral Part No: 130018090052; Package: 0402; Part_type: FILTER; Project: TI_J7_SVB-DUT; RoHS: NA; Temperature: NA; Tolerance: NA; Voltage: 6.3V; Wattage: NA; Weight: NA; Datasheet: Y:\MIS_DATABASE\DATASHEETS\DISCRETES\INDUCTORS\NFM15CC223C1A3.PDF
C302 C304 C305 C373 C377 C378 = CAP: CAP CERAMIC 10uF 10V 20% X5R 0402; Chkd/date: MANIRAJA/300520; Crtd /date: ALVY/260520; Custom_Duty: 15%; Customs_HS_Code: 85322990; Distributor_name: DIGIKEY; Distributor_part_number: 490-GRM155R61A106ME11DTR-ND; Footprint Path: Y:\MIS_DATABASE\Library\ALTIUM_TOOL\PCB_FOOTPRINTS\Altium_Footprint_Lib.PcbLib; Height: 0.55MM; Library Path: Y:\MIS_DATABASE\Library\ALTIUM_TOOL\SCHEMATICS_PARTS\MS_DISCRETE_Library.schlib; Mfr_name: MURATA; Mfr_part_number: GRM155R61A106ME11D; Mistral Part No: 120013110019-R; Package: 0402; Part_type: CAPACITORS\CERAMIC; Project: QCS610_NANOSOM; RoHS: RoHS; Temperature: -55°C+85°C; Tolerance: 20%; Voltage: 10V; Wattage: NA; Weight: 3.1mg; Datasheet: Y:\MIS_DATABASE\DATASHEETS\CAPACITORS\MURATA-GXX-SER_NOV17.PDF
C303 C309 C320-C325 C328 C331-C333 C335-C337 C342 C343 C347 C348 C351-C353 C355 C359 C362 C364 C366 C367 C370 C374 = CAP: CAP CERAMIC 0.1uF 16V 10% X5R 0201; Chkd/date: MANIRAJA/230118; Crtd /date: MANIRAJA/230118; Custom_Duty: 15%; Customs_HS_Code: 85322990; Distributor_name: DIGIKEY; Distributor_part_number: 490-14305-1-ND; Footprint Path: Y:\MIS_DATABASE\Library\ALTIUM_TOOL\PCB_FOOTPRINTS\Altium_Footprint_Lib.PcbLib; Height: 0.33MM; Library Path: Y:\MIS_DATABASE\Library\ALTIUM_TOOL\SCHEMATICS_PARTS\MS_DISCRETE_Library.schlib; Mfr_name: MURATA; Mfr_part_number: GRM033R61C104KE14D; Mistral Part No: 120009030072-R; Package: 0201; Part_type: CAPACITORS\CERAMIC; Project: TI_MAXIE_CPB; RoHS: RoHS; Temperature: -55°C+85°C; Tolerance: 10%; Voltage: 16V; Wattage: NA; Weight: 0.33mg; Datasheet: Y:\MIS_DATABASE\DATASHEETS\CAPACITORS\GRM033R61C104KE14.PDF
C306 C315 C341 C345 C363 C365 = CAP: CAP CERAMIC 1000pF 10V 10% X7R 0201; Chkd/date: VASANTHA/010117; Crtd /date: MAZHAR/160807; Custom_Duty: 15%; Customs_HS_Code: 85322990; Distributor_name: DIGIKEY; Distributor_part_number: 0201ZC102KAT2A-ND; Footprint Path: Y:\MIS_DATABASE\Library\ALTIUM_TOOL\PCB_FOOTPRINTS\Altium_Footprint_Lib.PcbLib; Height: 0.33MM; Library Path: Y:\MIS_DATABASE\Library\ALTIUM_TOOL\SCHEMATICS_PARTS\MS_DISCRETE_Library.schlib; Mfr_name: AVX CORPORATION; Mfr_part_number: 0201ZC102KAT2A; Mistral Part No: 120009030143-R; Package: 0201; Part_type: CAPACITORS\CERAMIC; Project: V8TS; RoHS: RoHS; Temperature: -55°C+125°C; Tolerance: 10%; Voltage: 10V; Wattage: NA; Weight: 0.17mg; Datasheet: Y:\MIS_DATABASE\DATASHEETS\CAPACITORS\AVX_MLC.PDF
C308 C314 C316 C338 C369 C375 = CAP: CAP CERAMIC 0.01uF 25V 10% X7R 0201; Chkd/date: MANIRAJA/080519; Crtd /date: ALVY/080519; Custom_Duty: 15%; Customs_HS_Code: 85322990; Distributor_name: DIGIKEY; Distributor_part_number: 490-14454-1-ND; Footprint Path: Y:\MIS_DATABASE\Library\ALTIUM_TOOL\PCB_FOOTPRINTS\Altium_Footprint_Lib.PcbLib; Height: 0.33MM; Library Path: Y:\MIS_DATABASE\Library\ALTIUM_TOOL\SCHEMATICS_PARTS\MS_DISCRETE_Library.schlib; Mfr_name: MURATA; Mfr_part_number: GRM033R71E103KE14D; Mistral Part No: 120019050002-R; Package: 0201; Part_type: CAPACITORS\CERAMIC; Project: BRUKER_SD820_COMMONDO; RoHS: RoHS; Temperature: -55°C+125°C; Tolerance: 10%; Voltage: 25V; Wattage: NA; Weight: 0.33mg; Datasheet: Y:\MIS_DATABASE\DATASHEETS\CAPACITORS\GRM033R71E103KE14.PDF
R119 R122 R349 = RESISTOR: RES 240E 1/10W 1% 0402; Chkd/date: MAZHAR/150611; Crtd /date: BAVISH/020611; Custom_Duty: 15%; Customs_HS_Code: 85332119; Distributor_name: DIGIKEY; Distributor_part_number: P240LCT-ND; Footprint Path: Y:\MIS_DATABASE\Library\ALTIUM_TOOL\PCB_FOOTPRINTS\Altium_Footprint_Lib.PcbLib; Height: 0.40MM; Library Path: Y:\MIS_DATABASE\Library\ALTIUM_TOOL\SCHEMATICS_PARTS\MS_DISCRETE_Library.schlib; Mfr_name: PANASONIC-ECG; Mfr_part_number: ERJ-2RKF2400X; Mistral Part No: 110011060017-R; Package: 0402; Part_type: RESISTORS\FIXED; Project: AM4515_EVM_LCD; RoHS: RoHS; Temperature: -55°C+155°C; Tolerance: 1%; Voltage: NA; Wattage: 1/10W; Weight: 0.8mg; Datasheet: Y:\MIS_DATABASE\DATASHEETS\RESISTORS\PAN-ERJSER_NOV17.PDF
R350 = RESISTOR: RES 10K 1/16W 5% 0402; Chkd/date: VASANTHA/061216; Crtd /date: MAZHAR/230805; Custom_Duty: 15%; Customs_HS_Code: 85332119; Distributor_name: DIGIKEY; Distributor_part_number: 311-10KJRCT-ND; Footprint Path: Y:\MIS_DATABASE\Library\ALTIUM_TOOL\PCB_FOOTPRINTS\Altium_Footprint_Lib.PcbLib; Height: 0.40MM; Library Path: Y:\MIS_DATABASE\Library\ALTIUM_TOOL\SCHEMATICS_PARTS\MS_DISCRETE_Library.schlib; Mfr_name: YAGEO AMERICA; Mfr_part_number: RC0402JR-0710KL; Mistral Part No: 110011060021-R; Package: 0402; Part_type: RESISTORS\FIXED; Project: HSE; RoHS: RoHS; Temperature: -55°C+155°C; Tolerance: 5%; Voltage: NA; Wattage: 1/16W; Weight: 0.65mg; Datasheet: Y:\MIS_DATABASE\DATASHEETS\RESISTORS\RCXXXXL-SER_MAR18.PDF
R352 R369 R370 = RESISTOR: RES 2.2K 1/16W 5% 0402; Chkd/date: VASANTHA/061216; Crtd /date: BAVISH/021210; Custom_Duty: 15%; Customs_HS_Code: 85332119; Distributor_name: DIGIKEY; Distributor_part_number: 311-2.2KJRCT-ND; Footprint Path: Y:\MIS_DATABASE\Library\ALTIUM_TOOL\PCB_FOOTPRINTS\Altium_Footprint_Lib.PcbLib; Height: 0.40MM; Library Path: Y:\MIS_DATABASE\Library\ALTIUM_TOOL\SCHEMATICS_PARTS\MS_DISCRETE_Library.schlib; Mfr_name: YAGEO AMERICA; Mfr_part_number: RC0402JR-072K2L; Mistral Part No: 110010120018-R; Package: 0402; Part_type: RESISTORS\FIXED; Project: TE4; RoHS: RoHS; Temperature: -55°C+155°C; Tolerance: 5%; Voltage: NA; Wattage: 1/16W; Weight: 0.65mg; Datasheet: Y:\MIS_DATABASE\DATASHEETS\RESISTORS\RCXXXXL-SER_MAR18.PDF
U26 = MT53D1024M32D4DT_VFBGA200: IC 4GB AUTO LPDDR4/LPDDR4x SDRAM TFBGA200; Crtd /date: TAMILARASU/141122; Custom_Duty: 15%; Customs_HS_Code: 85423100; Distributor_name: NA; Distributor_part_number: NA; Footprint Path: Y:\MIS_DATABASE\Library\ALTIUM_TOOL\PCB_FOOTPRINTS\Altium_Footprint_Lib.PcbLib; Height: 1.14MM; Library Path: Y:\MIS_DATABASE\Library\ALTIUM_TOOL\SCHEMATICS_PARTS\MS_MISCMEMORY_Library.schlib; Mfr_name: MICRON; Mistral Part No: 141122110001-R; Package: TFBGA200; Part_type: ICS\DIGITAL\MEMORY; Project: AM62A_EVM_BRD; RoHS: RoHS; Temperature: -40°C+125°C; Tolerance: NA; Voltage: NA; Wattage: NA; Weight: NA; Datasheet: Y:\MIS_DATABASE\DATASHEETS\ICS\MEMORY\MT53EX-A-AUTO-SER.PDF
U18 = AM62A-EVM_SOC_FCBGA484: IC AM62A SK EVM SoC MICROPROCESSOR FCBGA484; Chkd/date: PRADEEP/020823; Crtd /date: PRADEEP/020823; Custom_Duty: 15%; Customs_HS_Code: 85423100; Distributor_name: NA; Distributor_part_number: NA; Footprint Path: Y:\MIS_DATABASE\Library\ALTIUM_TOOL\PCB_FOOTPRINTS\Altium_Footprint_Lib.PcbLib; Height: 2.65MM; Library Ref: AM62A-EVM_SoC_FCBGA484; Mfr_name: TEXAS INSTRUMENTS; Mistral Part No: 141230080001-R; Package: FCBGA484; Part_type: ICS\DIGITAL\MICROPROCESSOR; Project: TI_AM62A_SK_EVM; RoHS: NA; Temperature: NA; Tolerance: NA; Voltage: NA; Wattage: NA; Weight: NA; Datasheet: Y:\MIS_DATABASE\DATASHEETS\ICS\DIGITAL\MICROCONTROLLER\AM62A_SK_EVM.PDF

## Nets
DGND: C30.2 C31.2 C32.2 C41.2 C44.2 C46.2 C47.2 C51.2 C56.2 C68.2 C214.2 C215.2 C216.2 C217.2 C218.2 C220.2 C221.2 C222.2 C223.2 C224.2 C225.2 C226.2 C227.2 C228.2 C229.2 C231.2 C232.2 C233.2 C234.2 C235.2 C236.2 C237.2 C238.2 C239.2 C240.2 C241.2 C243.2 C244.2 C245.2 C246.2 C247.2 C248.2 C250.2 C251.2 C252.2 C253.2 C254.2 C255.2 C257.2 C258.2 C259.2 C260.2 C261.2 C262.2 C263.2 C264.2 C265.2 C266.2 C268.2 C269.2 C270.2 C271.2 C272.2 C273.2 C274.2 C275.2 C276.2 C277.2 C278.2 C279.2 C280.2 C282.2 C283.2 C284.2 C285.2 C286.2 C287.2 C288.2 C289.2 C290.2 C291.2 C292.2 C294.2 C295.2 C298.2 C299.2 C302.2 C303.2 C304.2 C305.2 C306.2 C308.1 C309.2 C314.1 C315.2 C316.1 C320.2 C321.2 C322.2 C323.2 C324.2 C325.2 C328.2 C331.2 C332.2 C333.2 C335.2 C336.2 C337.2 C338.1 C341.2 C342.2 C343.2 C345.2 C347.2 C348.2 C351.2 C352.2 C353.2 C355.2 C359.2 C362.2 C363.2 C364.2 C365.2 C366.2 C367.2 C369.1 C370.2 C373.2 C374.2 C375.1 C377.2 C378.2 C507.2 C508.2(GND) C509.2(GND) C510.2(GND) C511.2(GND) C512.2(GND) C513.2(GND) C514.2(GND) C515.2(GND) C516.2(GND) C517.2(GND) C518.2(GND) C519.2(GND) C520.2(GND) C521.2(GND) C522.2(GND) C523.2(GND) C524.2(GND) C525.2(GND) C526.2(GND) C527.2(GND) C528.2(GND) C529.2(GND) R332.2 R349.2 R350.1 U18.A1(VSS) U18.A4(VSS) U18.A6(VSS) U18.A10(VSS) U18.A13(VSS) U18.A18(VSS) U18.A22(VSS) U18.AA2(VSS) U18.AA4(VSS) U18.AA8(VSS) U18.AA11(VSS) U18.AA14(VSS) U18.AB1(VSS) U18.AB3(VSS) U18.AB5(VSS) U18.AB9(VSS) U18.AB12(VSS) U18.AB15(VSS) U18.AB18(VSS) U18.AB22(VSS) U18.B3(VSS) U18.B5(VSS) U18.B7(VSS) U18.C4(VSS) U18.D2(VSS) U18.D4(VSS) U18.D11(VSS) U18.D20(VSS) U18.E1(VSS) U18.E3(VSS) U18.E5(VSS) U18.F2(VSS) U18.F4(VSS) U18.F11(VSS) U18.F13(VSS) U18.F16(VSS) U18.G3(VSS) U18.G5(VSS) U18.G9(VSS) U18.G12(VSS) U18.G17(VSS) U18.H1(VSS) U18.H4(VSS) U18.H11(VSS) U18.H14(VSS) U18.H20(VSS) U18.J3(VSS) U18.J12(VSS) U18.J17(VSS) U18.K1(VSS) U18.K4(VSS) U18.K7(VSS) U18.K9(VSS) U18.K11(VSS) U18.L3(VSS) U18.L12(VSS) U18.L14(VSS) U18.L20(VSS) U18.M4(VSS) U18.M7(VSS) U18.M11(VSS) U18.M17(VSS) U18.N1(VSS) U18.N8(VSS) U18.N10(VSS) U18.N12(VSS) U18.N14(VSS) U18.N16(VSS) U18.P7(VSS) U18.P11(VSS) U18.P13(VSS) U18.P15(VSS) U18.P17(VSS) U18.P20(VSS) U18.R2(VSS) U18.R4(VSS) U18.R6(VSS) U18.R10(VSS) U18.R12(VSS) U18.R14(VSS) U18.R16(VSS) U18.T1(VSS) U18.T3(VSS) U18.T5(VSS) U18.T7(VSS) U18.T15(VSS) U18.T17(VSS) U18.U2(VSS) U18.U4(VSS) U18.U6(VSS) U18.U9(VSS) U18.U12(VSS) U18.U14(VSS) U18.U16(VSS) U18.V1(VSS) U18.V3(VSS) U18.V5(VSS) U18.V7(VSS) U18.V9(VSS) U18.V20(VSS) U18.W2(VSS) U18.W4(VSS) U18.W6(VSS) U18.W8(VSS) U18.W11(VSS) U18.W14(VSS) U18.Y3(VSS) U18.Y5(VSS) U18.Y9(VSS) U18.Y12(VSS) U18.Y15(VSS) U21.A1(GND) U26.A3(VSS) U26.A10(VSS) U26.AB3(VSS) U26.AB5(VSS) U26.AB8(VSS) U26.AB10(VSS) U26.C1(VSS) U26.C5(VSS) U26.C8(VSS) U26.C12(VSS) U26.D2(VSS) U26.D4(VSS) U26.D9(VSS) U26.D11(VSS) U26.E1(VSS) U26.E5(VSS) U26.E8(VSS) U26.E12(VSS) U26.G1(VSS) U26.G3(VSS) U26.G5(VSS) U26.G8(VSS) U26.G10(VSS) U26.G12(VSS) U26.J1(VSS) U26.J3(VSS) U26.J10(VSS) U26.J12(VSS) U26.K2(VSS) U26.K4(VSS) U26.K9(VSS) U26.K11(VSS) U26.N2(VSS) U26.N4(VSS) U26.N9(VSS) U26.N11(VSS) U26.P1(VSS) U26.P3(VSS) U26.P10(VSS) U26.P12(VSS) U26.T1(VSS) U26.T3(VSS) U26.T5(VSS) U26.T8(VSS) U26.T10(VSS) U26.T12(VSS) U26.V1(VSS) U26.V5(VSS) U26.V8(VSS) U26.V12(VSS) U26.W2(VSS) U26.W4(VSS) U26.W9(VSS) U26.W11(VSS) U26.Y1(VSS) U26.Y5(VSS) U26.Y8(VSS) U26.Y12(VSS) ; also on sheet 9 10 11 12 13 17 18 19 20 21 22 23 24 25 26 27 28 29 30 31 32 33 34 35 36 37 38 39 40 41 42 43
VCC_3V3_MAIN: C51.1 C280.1 FL13.1 R80.1 R574.1 U21.B2(VIN) ; also on sheet 11 12 25
VDD1_LPDDR4_1V8: C302.1 C309.1 C314.2 C322.1 C328.1 C345.1 C355.1 C363.1 C370.1 C374.1 C375.2 C378.1 FL12.2 U26.F1(VDD1) U26.F12(VDD1) U26.G4(VDD1) U26.G9(VDD1) U26.T4(VDD1) U26.T9(VDD1) U26.U1(VDD1) U26.U12(VDD1)
VDD_CANUART: C47.1 C277.1 R95.2 U18.H9(VDD_CANUART)
VDD_CANUART_EN: R574.2 U21.A2(EN) ; also on sheet 12
VDD_CORE: C227.1 C234.1 C246.1 C248.1 C255.1 C260.1 C274.1 C508.1(INPUT) C508.3(OUTPUT) C509.1(INPUT) C509.3(OUTPUT) C510.1(INPUT) C510.3(OUTPUT) C511.1(INPUT) C511.3(OUTPUT) C512.1(INPUT) C512.3(OUTPUT) C513.1(INPUT) C513.3(OUTPUT) C514.1(INPUT) C514.3(OUTPUT) FL3.1 FL4.1 FL9.2 U18.J9(VDD_CORE) U18.J11(VDD_CORE) U18.J13(VDD_CORE) U18.J15(VDD_CORE) U18.K14(VDD_CORE) U18.L9(VDD_CORE) U18.L11(VDD_CORE) U18.L13(VDD_CORE) U18.M12(VDD_CORE) U18.N11(VDD_CORE) U18.N13(VDD_CORE) U18.P10(VDD_CORE) U18.P14(VDD_CORE) U18.R9(VDD_CORE) U18.R15(VDD_CORE) U18.T16(VDD_CORE) U18.U15(VDD_CORE) ; also on sheet 12 13
VDD_LPDDR4: C294.1 C295.1 C298.1 C299.1 C303.1 C304.1 C305.1 C306.1 C308.2 C315.1 C316.2 C320.1 C321.1 C323.1 C324.1 C325.1 C331.1 C332.1 C333.1 C335.1 C336.1 C337.1 C338.2 C341.1 C342.1 C343.1 C347.1 C348.1 C351.1 C352.1 C353.1 C359.1 C362.1 C364.1 C365.1 C366.1 C367.1 C369.2 C373.1 C377.1 C517.1(INPUT) C517.3(OUTPUT) C518.1(INPUT) C518.3(OUTPUT) C519.1(INPUT) C519.3(OUTPUT) C520.1(INPUT) C520.3(OUTPUT) C521.1(INPUT) C521.3(OUTPUT) C524.1(INPUT) C524.3(OUTPUT) C525.1(INPUT) C525.3(OUTPUT) R119.1 R122.1 R352.2 R369.2 R370.2 U18.A2(VDDS_DDR) U18.AA1(VDDS_DDR) U18.AB2(VDDS_DDR) U18.B1(VDDS_DDR) U18.J7(VDDS_DDR) U18.K8(VDDS_DDR) U18.L7(VDDS_DDR) U18.L8(VDDS_DDR_C) U18.M8(VDDS_DDR) U18.N7(VDDS_DDR) U18.P8(VDDS_DDR) U26.A4(VDD2) U26.A9(VDD2) U26.AA3(VDDQ) U26.AA5(VDDQ) U26.AA8(VDDQ) U26.AA10(VDDQ) U26.AB4(VDD2) U26.AB9(VDD2) U26.B3(VDDQ) U26.B5(VDDQ) U26.B8(VDDQ) U26.B10(VDDQ) U26.D1(VDDQ) U26.D5(VDDQ) U26.D8(VDDQ) U26.D12(VDDQ) U26.F3(VDDQ) U26.F5(VDD2) U26.F8(VDD2) U26.F10(VDDQ) U26.H1(VDD2) U26.H5(VDD2) U26.H8(VDD2) U26.H12(VDD2) U26.K1(VDD2) U26.K3(VDD2) U26.K10(VDD2) U26.K12(VDD2) U26.N1(VDD2) U26.N3(VDD2) U26.N10(VDD2) U26.N12(VDD2) U26.R1(VDD2) U26.R5(VDD2) U26.R8(VDD2) U26.R12(VDD2) U26.U3(VDDQ) U26.U5(VDD2) U26.U8(VDD2) U26.U10(VDDQ) U26.W1(VDDQ) U26.W5(VDDQ) U26.W8(VDDQ) U26.W12(VDDQ) ; also on sheet 12 13
VDDA_1V8: C30.1 C214.1 C215.1 C216.1 C228.1 C263.1 C266.1 C515.1(INPUT) C515.3(OUTPUT) C516.1(INPUT) C516.3(OUTPUT) FL7.1 FL8.1 FL10.1 U18.G18(VDDA_TEMP1) U18.L10(VDDA_TEMP2) U18.P16(VDDA_TEMP0) U18.T10(VDDA_1P8_USB) ; also on sheet 13 24
VDDA_1V8_FB1: C44.1 C46.1 C243.1 C245.1 C262.1 C265.1 C278.1 FL8.2 U18.J10(VDDA_MCU) U18.K10(VDDA_PLL4) U18.K13(VDDA_PLL3) U18.M13(VDDA_PLL2) U18.N9(VDDA_PLL0) U18.R11(VDDA_PLL1)
VDDA_1V8_FB2: C236.1 C254.1 FL7.2 U18.T12(VDDA_1P8_CSIRX0)
VDDA_1V8_FB_OSC: C56.1 C286.1 FL10.2 U18.J8(VDDS_OSC0)
VDDA_DDR_PLL0: C269.1 C289.1 C292.1 FL9.1 U18.M9(VDDA_DDR_PLL0)
VDDA_SYS_MON: R80.2 R332.1 U18.H12(VMON_VSYS)
VDDR_CORE: C68.1 C237.1 C250.1 C253.1 C268.1 C273.1 C526.1(INPUT) C526.3(OUTPUT) C527.1(INPUT) C527.3(OUTPUT) U18.J14(VDDR_CORE) U18.K12(VDDR_CORE) U18.M10(VDDR_CORE) U18.M14(VDDR_CORE) U18.P9(VDDR_CORE) U18.P12(VDDR_CORE) ; also on sheet 13 35
VDDSHV_SDIO: C31.1 R61.1 ; also on sheet 12 19
 VDDA_CORE_CSI: C251.1 C252.1 C259.1 C261.1 FL3.2 U18.T11(VDDA_CORE_CSIRX0)
 VDDA_CORE_USB: C271.1 C272.1 C275.1 FL4.2 U18.T9(VDDA_CORE_USB)
CAN_IO_3V3: C282.1 C283.1 FL13.2 U18.H8(VDDSHV_CANUART) ; also on sheet 12 30 33 43
CAP_VDDS0: C241.1 U18.G13(CAP_VDDS0)
CAP_VDDS1: C222.1 U18.K16(CAP_VDDS1)
CAP_VDDS2: C235.1 U18.T14(CAP_VDDS2)
CAP_VDDS3: C220.1 U18.M16(CAP_VDDS3)
CAP_VDDS4: C285.1 U18.R8(CAP_VDDS4)
CAP_VDDS5: C231.1 U18.G15(CAP_VDDS5)
CAP_VDDS6: C223.1 U18.J16(CAP_VDDS6)
CAP_VDDS_CANUART: C287.1 U18.G8(CAP_VDDS_CANUART)
CAP_VDDS_MCU: C264.1 U18.G10(CAP_VDDS_MCU)
LPDDR4_CA0: U18.J5(DDR0_A0) U26.H2(CA0_A) U26.R2(CA0_B)
LPDDR4_CA1: U18.J2(DDR0_A1) U26.J2(CA1_A) U26.P2(CA1_B)
LPDDR4_CA2: U18.J4(DDR0_A2) U26.H9(CA2_A) U26.R9(CA2_B)
LPDDR4_CA3: U18.L4(DDR0_A3) U26.H10(CA3_A) U26.R10(CA3_B)
LPDDR4_CA4: U18.J1(DDR0_A4) U26.H11(CA4_A) U26.R11(CA4_B)
LPDDR4_CA5: U18.K5(DDR0_A5) U26.J11(CA5_A) U26.P11(CA5_B)
LPDDR4_CAL0: R349.1 U18.H6(DDR0_CAL0)
LPDDR4_CK_N: U18.L1(DDR0_CK0_N) U26.J9(CK_C_A) U26.P9(CK_C_B)
LPDDR4_CK_P: U18.M1(DDR0_CK0) U26.J8(CK_T_A) U26.P8(CK_T_B)
LPDDR4_CKE0: U18.P3(DDR0_CKE0) U26.J4(CKE0_A) U26.P4(CKE0_B)
LPDDR4_CKE1: U18.P5(DDR0_CKE1) U26.J5(CKE1_A) U26.P5(CKE1_B)
LPDDR4_CS0_A: U18.J6(DDR0_CS0_N) U26.H4(CS0_A)
LPDDR4_CS0_B: U18.M6(DDR0_RAS_N) U26.R4(CS0_B)
LPDDR4_CS1_A: U18.N4(DDR0_CS1_N) U26.H3(CS1_A)
LPDDR4_CS1_B: U18.M5(DDR0_CAS_N) U26.R3(CS1_B)
LPDDR4_DMI0: U18.C2(DDR0_DM0) U26.C3(DMI0_A)
LPDDR4_DMI1: U18.F3(DDR0_DM1) U26.C10(DMI1_A)
LPDDR4_DMI2: U18.U1(DDR0_DM2) U26.Y3(DMI0_B)
LPDDR4_DMI3: U18.W3(DDR0_DM3) U26.Y10(DMI1_B)
LPDDR4_DQ0: U18.A5(DDR0_DQ0) U26.B2(DQ0_A)
LPDDR4_DQ1: U18.B4(DDR0_DQ1) U26.C2(DQ1_A)
LPDDR4_DQ2: U18.B6(DDR0_DQ2) U26.E2(DQ2_A)
LPDDR4_DQ3: U18.D5(DDR0_DQ3) U26.F2(DQ3_A)
LPDDR4_DQ4: U18.C5(DDR0_DQ4) U26.F4(DQ4_A)
LPDDR4_DQ5: U18.C3(DDR0_DQ5) U26.E4(DQ5_A)
LPDDR4_DQ6: U18.B2(DDR0_DQ6) U26.C4(DQ6_A)
LPDDR4_DQ7: U18.A3(DDR0_DQ7) U26.B4(DQ7_A)
LPDDR4_DQ8: U18.E2(DDR0_DQ8) U26.B11(DQ8_A)
LPDDR4_DQ9: U18.F5(DDR0_DQ9) U26.C11(DQ9_A)
LPDDR4_DQ10: U18.E6(DDR0_DQ10) U26.E11(DQ10_A)
LPDDR4_DQ11: U18.G2(DDR0_DQ11) U26.F11(DQ11_A)
LPDDR4_DQ12: U18.G6(DDR0_DQ12) U26.F9(DQ12_A)
LPDDR4_DQ13: U18.G4(DDR0_DQ13) U26.E9(DQ13_A)
LPDDR4_DQ14: U18.E4(DDR0_DQ14) U26.C9(DQ14_A)
LPDDR4_DQ15: U18.D3(DDR0_DQ15) U26.B9(DQ15_A)
LPDDR4_DQ16: U18.T6(DDR0_DQ16) U26.AA2(DQ0_B)
LPDDR4_DQ17: U18.T4(DDR0_DQ17) U26.Y2(DQ1_B)
LPDDR4_DQ18: U18.U5(DDR0_DQ18) U26.V2(DQ2_B)
LPDDR4_DQ19: U18.R5(DDR0_DQ19) U26.U2(DQ3_B)
LPDDR4_DQ20: U18.P2(DDR0_DQ20) U26.U4(DQ4_B)
LPDDR4_DQ21: U18.R3(DDR0_DQ21) U26.V4(DQ5_B)
LPDDR4_DQ22: U18.T2(DDR0_DQ22) U26.Y4(DQ6_B)
LPDDR4_DQ23: U18.U3(DDR0_DQ23) U26.AA4(DQ7_B)
LPDDR4_DQ24: U18.Y2(DDR0_DQ24) U26.AA11(DQ8_B)
LPDDR4_DQ25: U18.V2(DDR0_DQ25) U26.Y11(DQ9_B)
LPDDR4_DQ26: U18.V4(DDR0_DQ26) U26.V11(DQ10_B)
LPDDR4_DQ27: U18.W5(DDR0_DQ27) U26.U11(DQ11_B)
LPDDR4_DQ28: U18.Y4(DDR0_DQ28) U26.U9(DQ12_B)
LPDDR4_DQ29: U18.AA3(DDR0_DQ29) U26.V9(DQ13_B)
LPDDR4_DQ30: U18.AA5(DDR0_DQ30) U26.Y9(DQ14_B)
LPDDR4_DQ31: U18.AB4(DDR0_DQ31) U26.AA9(DQ15_B)
LPDDR4_DQS0_N: U18.C1(DDR0_DQS0_N) U26.E3(DQS0_C_A)
LPDDR4_DQS0_P: U18.D1(DDR0_DQS0) U26.D3(DQS0_T_A)
LPDDR4_DQS1_N: U18.F1(DDR0_DQS1_N) U26.E10(DQS1_C_A)
LPDDR4_DQS1_P: U18.G1(DDR0_DQS1) U26.D10(DQS1_T_A)
LPDDR4_DQS2_N: U18.P1(DDR0_DQS2_N) U26.V3(DQS0_C_B)
LPDDR4_DQS2_P: U18.R1(DDR0_DQS2) U26.W3(DQS0_T_B)
LPDDR4_DQS3_N: U18.Y1(DDR0_DQS3_N) U26.V10(DQS1_C_B)
LPDDR4_DQS3_P: U18.W1(DDR0_DQS3) U26.W10(DQS1_T_B)
LPDDR4_ODT_CA_A: R370.1 U26.G2(ODT_CA_A)
LPDDR4_ODT_CA_B: R369.1 U26.T2(ODT_CA_B)
LPDDR4_RESET_N: R350.2 R352.1 U18.P6(DDR0_RESET0_N) U26.T11(RESET_N)
LPDDR4_ZQ0: R122.2 U26.A5(ZQ0)
LPDDR4_ZQ1: R119.2 U26.A8(ZQ1)
SOC_DVDD1V8: C32.1 C217.1 C218.1 C221.1 C225.1 C258.1 C279.1 C284.1 C528.1(INPUT) C528.3(OUTPUT) C529.1(INPUT) C529.3(OUTPUT) FL12.1 U18.F12(VMON_1P8_SOC) U18.H16(VDDSHV6) U18.H17(VDDSHV6) U18.K15(VDDSHV1) U18.L16(VDDSHV1) U18.T8(VDDSHV4) U18.U8(VDDSHV4) ; also on sheet 12 13
SoC_DVDD3V3: C41.1 C229.1 C232.1 C233.1 C238.1 C239.1 C240.1 C244.1 C247.1 C257.1 C270.1 C276.1 C522.1(INPUT) C522.3(OUTPUT) C523.1(INPUT) C523.3(OUTPUT) U18.F9(VMON_3P3_SOC) U18.G11(VDDSHV_MCU) U18.G14(VDDSHV0) U18.H10(VDDSHV_MCU) U18.H13(VDDSHV0) U18.L15(VDDSHV3) U18.M15(VDDSHV3) U18.N15(VDDSHV3) U18.R13(VDDSHV2) U18.T13(VDDSHV2) U18.U10(VDDA_3P3_USB) U18.U13(VDDSHV2) ; also on sheet 13
SoC_VDDSHV5_SDIO: C224.1 C226.1 R61.2 U18.G16(VDDSHV5) U18.H15(VDDSHV5)
TEMP_DIODE_P: TP99.1(TP) U18.F10(RSVD4)
VPP_1V8: C288.1 C290.1 C291.1 U18.F7(VPP) ; also on sheet 12
N23233575: C507.1 R95.1 U21.B1(VOUT)

Not connected (* = marked no-connect by the designer): U18 F6(RSVD3)* G7(RSVD5)* H2(DDR0_A7)* H3(DDR0_BA1)* H5(DDR0_ODT0)* H7(DDR0_ALERT_N)* K2(DDR0_A10)* K3(DDR0_A6)* K6(DDR0_BA0)* L2(DDR0_A9)* L5(DDR0_A11)* L6(DDR0_A8)* M2(DDR0_A13)* M3(DDR0_A12)* N2(DDR0_PAR)* N3(DDR0_ODT1)* N5(DDR0_ACT_N)* N6(DDR0_WE_N)* P4(DDR0_BG0)* R7(DDR0_BG1)*; U26 A1(DNU1)* A2(DNU2)* A11(DNU3)* A12(DNU4)* AA1(DNU7)* AA12(DNU8)* AB1(DNU9)* AB2(DNU10)* AB11(DNU11)* AB12(DNU12)* B1(DNU5)* B12(DNU6)* G11(NC1)* K5(NC2)* K8(NC3)* N5(NC4)* N8(NC5)*

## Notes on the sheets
sheet 14
- D-Note :-
  Recommend implementing the voltage monitoring functionality using VMON_VSYS for early
  detection of supply failure. It is meant to be a  power-fail indicator for the main
  input (higher)  voltage rail that enters the PCB.  For example, 5, 12, or 24 volts. The
  error associated with this monitor would require you to set the threshold significantly
  lower than the nominal to avoid false trigger. Refer System Power Supply Monitor Design
  Guidelines section of the data sheet
- SOC POWER
- D-Note :-
  Changing the core voltage is not allowed
  after the device has been released from
  reset. If you turn off the core supply, we
  expect you to turn off all power rails and
  ramp them down per the power-down sequence
  and wait until all supply rails decay
  below 300mv before turning on power again
- D-Note :-
  VDD_CORE and VDDR_CORE are
  recommended to be powered
  by the same source so they
  ramp together when VDD_CORE
  is operating at 0.85V
- 0.5V to VMON_VSYS pin
- D-Note :-
  Select capacitor with ESR < 1 O
  Ensure the PCB loop inductance is < 2.5 nH
  Select 0201 package or smallest possible package
  Refer SOC Data sheet
- D-Note :-
  Add a filter
  cap. Refer SOC
  data sheet
  section System
  Power Supply
  Monitor Design
  Guidelines
- D-Note :-
  Common SOC LVCMOS IO interface guidelines
  1. Most of the SOC IOs are not fail-safe. No input should be applied before supply ramps.
  2. SOC LVCMOS inputs have minimum slew rate requirements specified
  3. SOC IO buffers are off during Reset. A pull is required near to the attached device being
  driven by the SOC IOs
  4. Any SOC IO that has a trace connected  and not being actively driven needs a parallel pull.
  When adding pull is not feasible, ensure the traces are routed away from noisy signals
- D-Note :-
  A Trace connected to SOC  is effectively an antenna that will pick up noise.
  A potential will be generated on the signal when noise couples into the antenna.
  This potential will be largest on the highest impedance end of the signal.
  By placing a pull-up or pull-down near the SoC pin, we force the highest potential
  to the open-circuit end of the signal rather than the SoC end of the signal.
- D-Note :-
  Connecting 1.8V supply
  source directly to VPP
  continuously is not allowed
- R-Note :-
  Reserved pins Leave unconnected
- D-Note :-
  Refer pin connectivity table of the SOC data sheet for connecting the USB IO, analog and
  core supplies when USB interface is not used. It is acceptable to have the supplies
  connected and all the USB pins left unconnected provided the USB driver is not initialized
  any time and the USB calibration procedure does not happen. Grounding the USB supplies as
  per pin connectivity requirements when not used saves power when low power is a critical
  requirement.
- D-Note :-
  It is very important to select an LDO with very fast transient response
  and connect its output to the VPP pin with a low loop inductance path to
  ensure it is able to source the high transient load, where the VPP pin
  never drops below the minimum operating voltage.
- D-Note :-
  Refer Pin connectivity requirements to connect the CSI0
  supplies (analog and core) when CSI0 interface is not used
  Ferrite and Bulk Caps are optional when CSI0 is not used and
  Boundary scan functionality is required
- CORE SUPPLY
- 1.8V Analog SUPPLY
- VDDA_DDR_PLL0
- VDDA_CORE_USB
- VDDS_OSC0
- VDDA_1V8_CSIRX
- VDDA_PLL0..4, VDDA_MCU
- VDDA_CORE_CSI
- VDDSHV_CANUART
- BLM15PX121SN1D :- 120E
  2A @ 85 deg C
  1.1A @ 125 deg C
- VDD_CANUART
- VPP_1V8
- 3.3V/1.8V MMC1 SUPPLY
- VDDSHV5
- VDDA_3P3_USB
sheet 15
- SOC POWER SUPPLIES - DECAPS
- Cad Note:
  Place 0.1 uF caps near to SoC pins
- Cad Note:
  Place 0.1 uF caps near to SoC pins
- Cad Note:
  Place 0.1 uF caps near to SoC pins
- Cad Note:
  Place 0.1 uF caps near to SoC pins
- SOC VSS
- Cad Note:
  Place 0.1 uF caps near to SoC pins
- Cad Note:
  Place 0.1 uF caps near to SoC pins
- R-Note :-
  Use of 3 terminal caps optimizes
  use of bulk caps and minimizes the
  PCB inductance
sheet 16
- SOC LPDDR4 INTERFACE
- LPDDR4 POWER DECAPS
- VDDQ_LPDDR4_1V1
- VDD2_LPDDR4_1V1
- LPDDR4 DEVICE
- VDDQ_LPDDR4_1V1
- VDD2_LPDDR4_1V1
- R-Note :-
  Pulldown is populated
- D-Note :-
  10 K pulldown is
  recommended
  Refer Processor specific
  DDR design guide
